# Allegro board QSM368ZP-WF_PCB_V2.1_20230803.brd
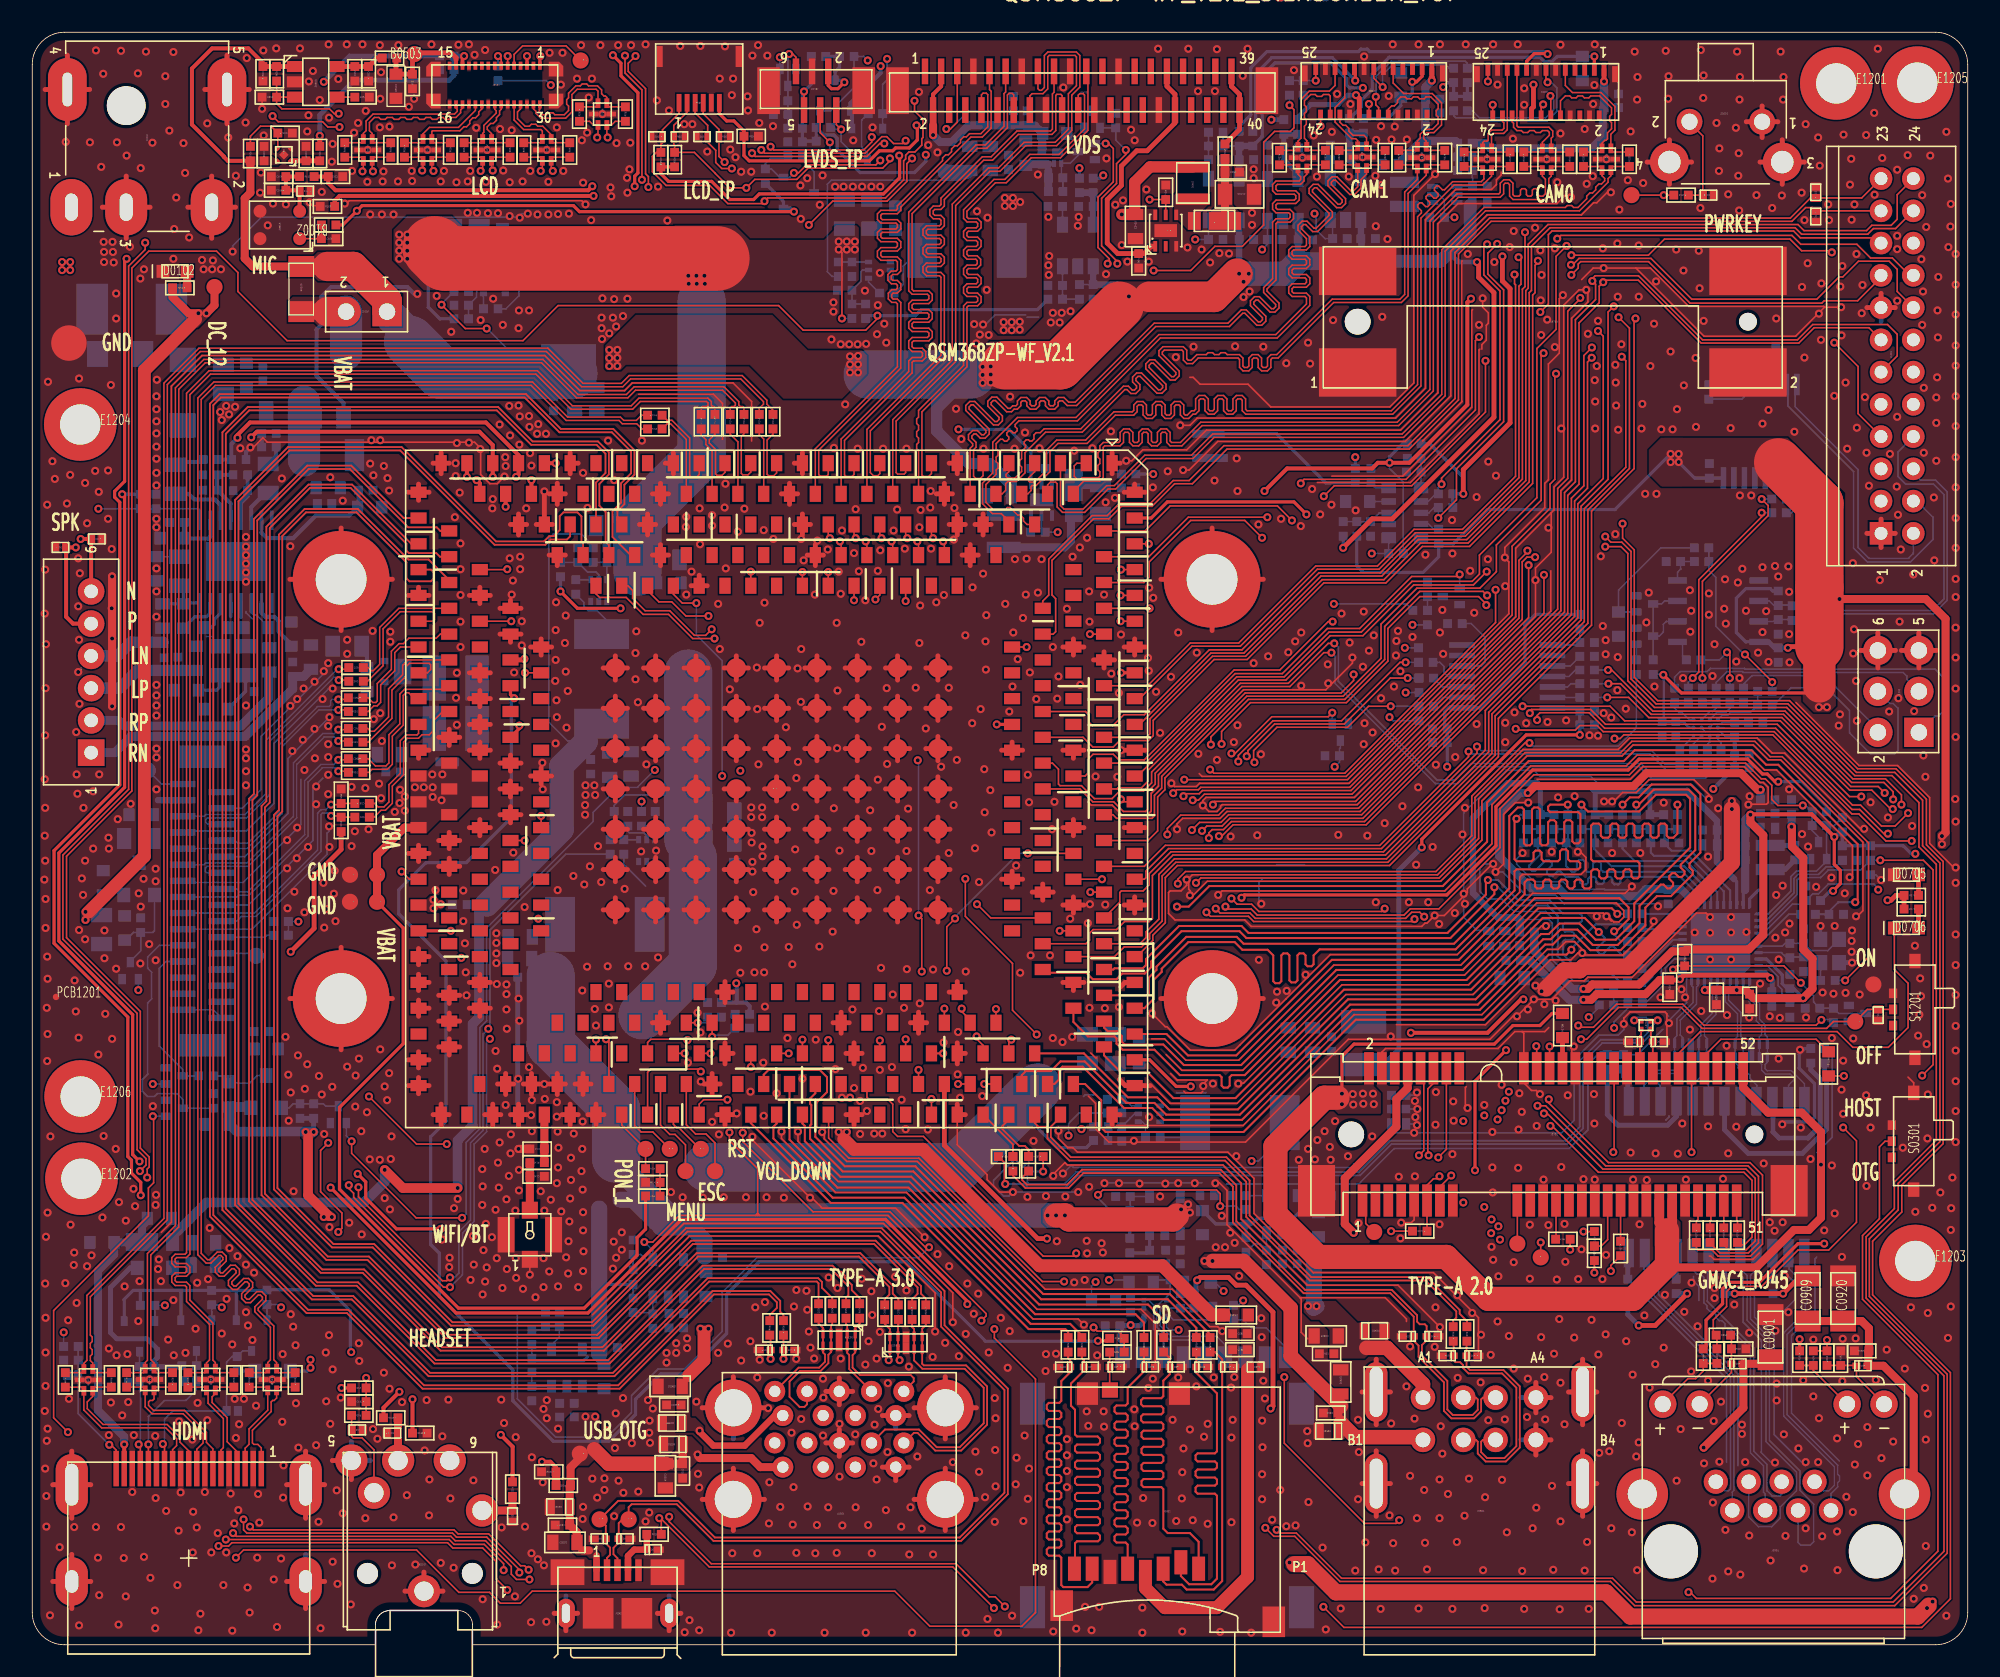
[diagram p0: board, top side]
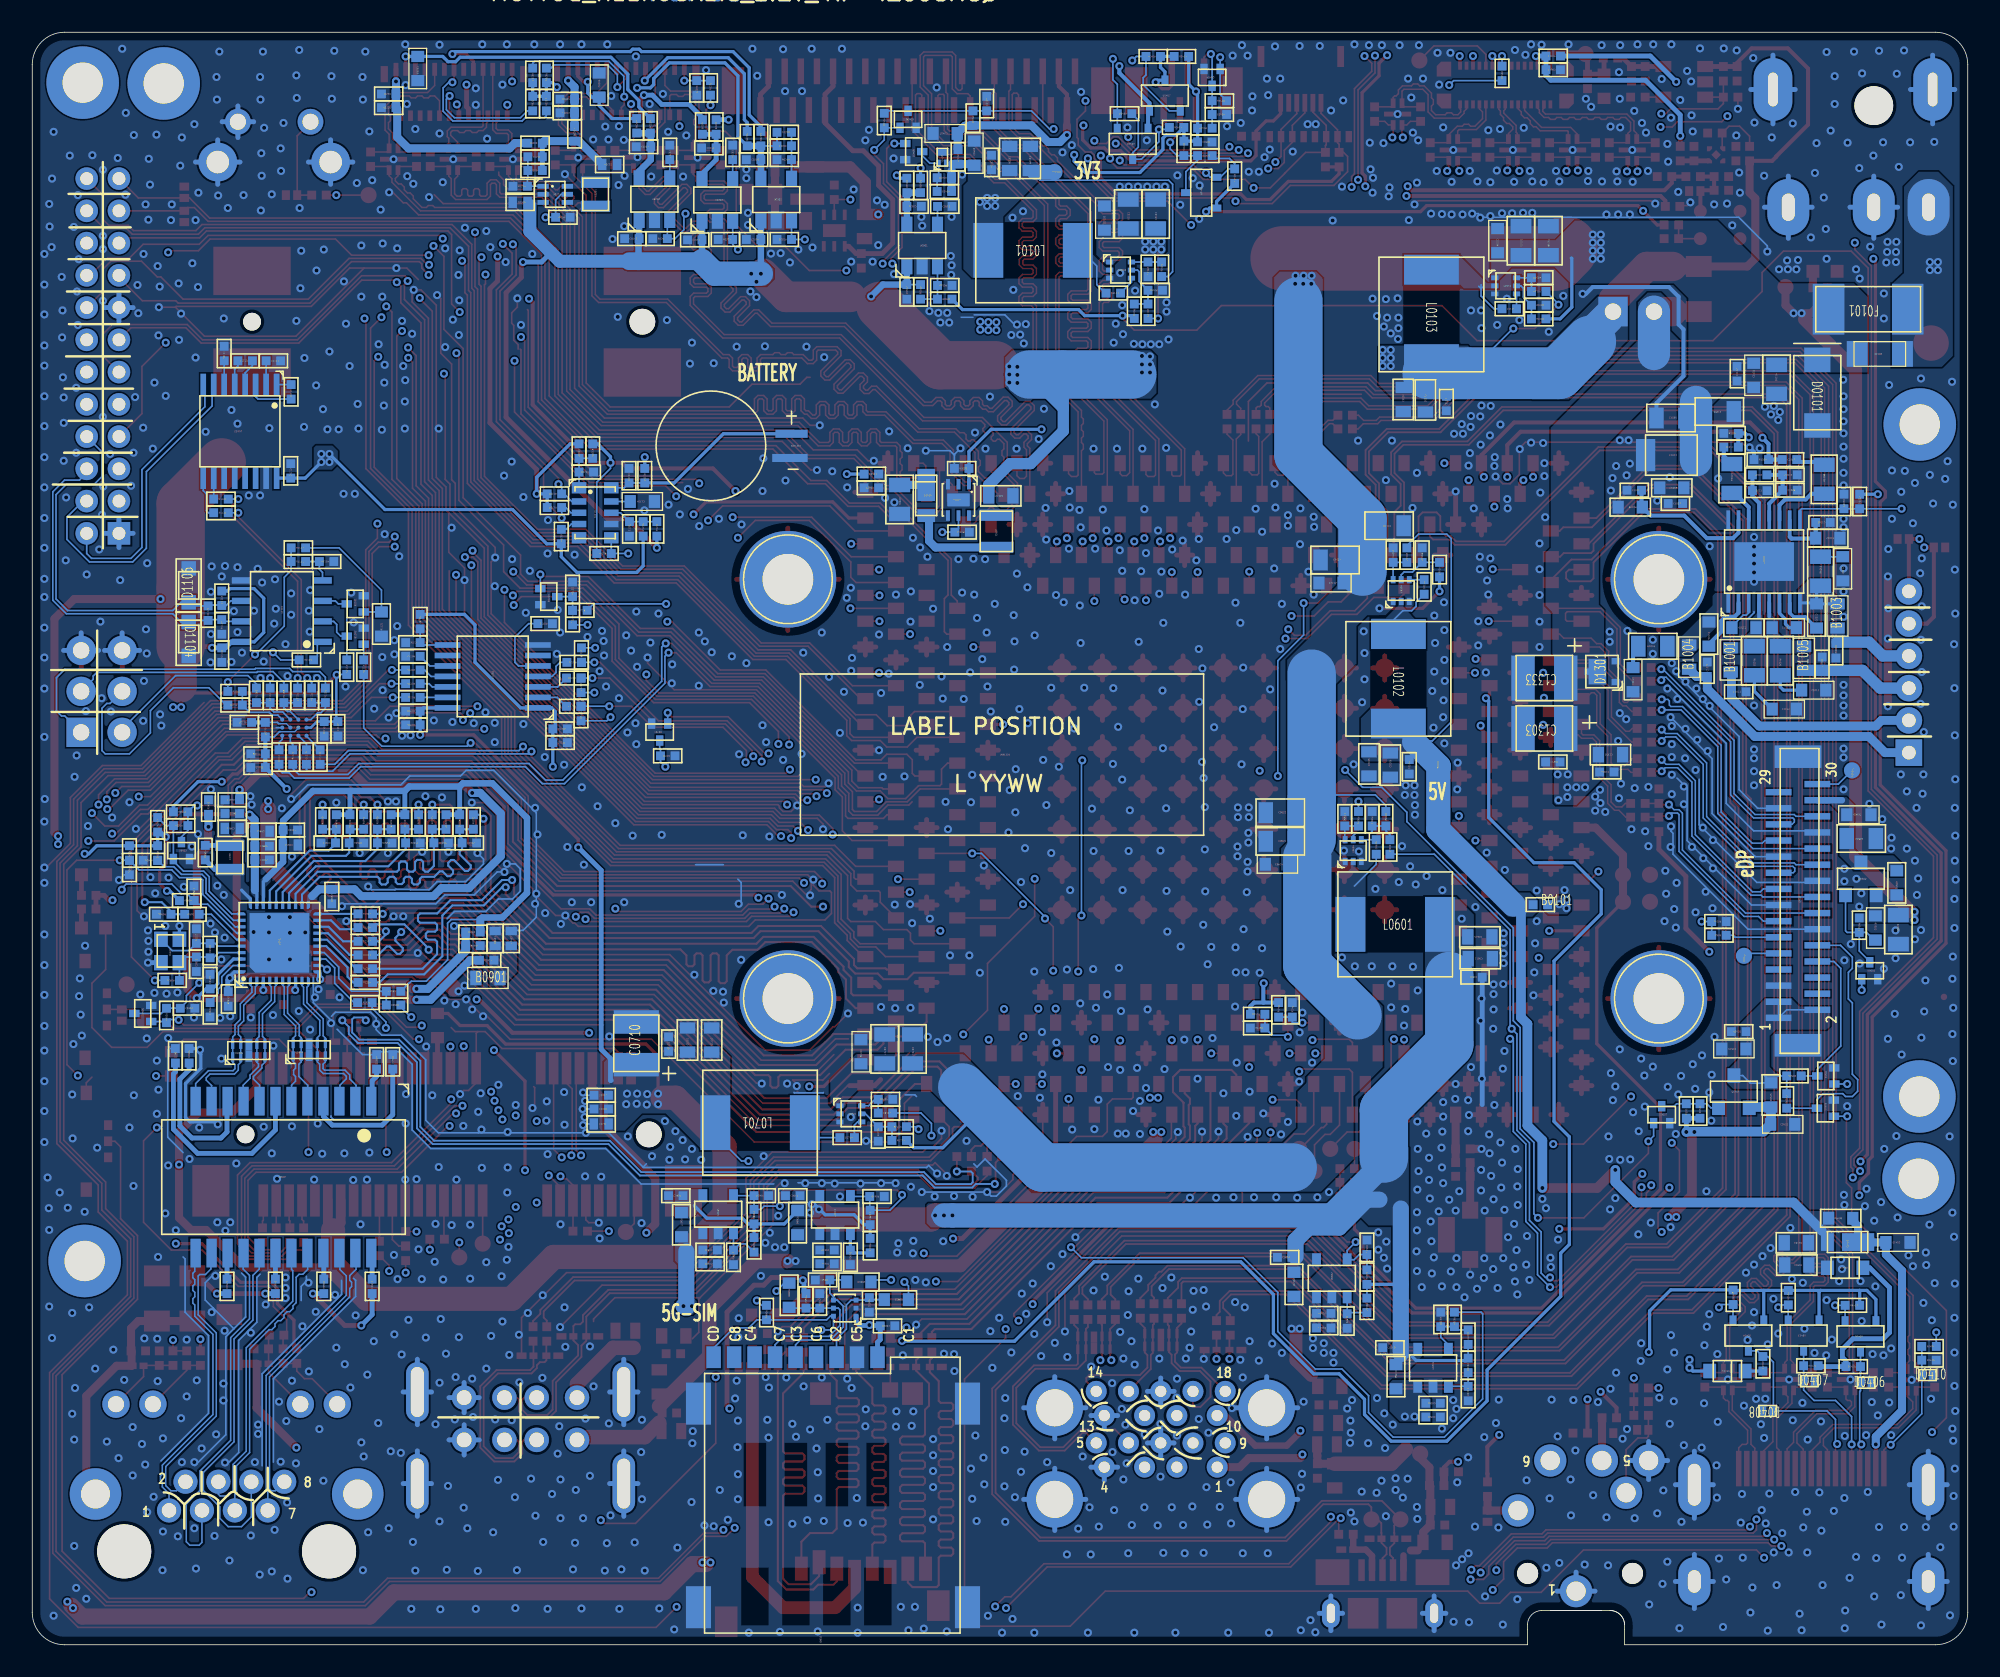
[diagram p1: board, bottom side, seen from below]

Outline 120 x 100 mm; copper layers: TOP, INNER LAYER 2, INNER LAYER 3, BOTTOM. Coordinates in mm from the lower left corner of the outline.
Outline path: 21.27,1.25 arc(21.55,1.87) 22.18,2.12 ; 21.27,1.25 arc(21.55,1.87) 22.18,2.12 ; 21.27,1.25 arc(21.27,1.09) 21.27,0.93 21.27,0 2,0 arc(0.59,0.59) 0,2 0,98 arc(0.59,99.41) 2,100 118,100 arc(119.41,99.41) 120,98 120,2 arc(119.41,0.59) 118,0 27.3,0 27.3,0.93 arc(27.3,1.09) 27.3,1.25 arc(27.03,1.87) 26.4,2.12 22.18,2.12 ; 22.68,2.12 25.9,2.12

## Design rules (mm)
net group 50OHM_ANTWIFI0: nets 50OHM_ANTWIFI0 50OHM_WIFI_ANT0
net group 50OHM_GMAC1_RXCLK_M1: nets 50OHM_GMAC1_RXCLK_M1 50OHM_RXC/PHYAD1_A
net group 50OHM_GMAC1_RXD0_M1: nets 50OHM_GMAC1_RXD0_M1 50OHM_RXD0/RXDLY_A
net group 50OHM_GMAC1_RXD1_M1: nets 50OHM_GMAC1_RXD1_M1 50OHM_RXD1/CFG_MODEO_A
net group 50OHM_GMAC1_RXD2_M1: nets 50OHM_GMAC1_RXD2_M1 50OHM_RXD2/CFG_MODE1_A
net group 50OHM_GMAC1_RXD3_M1: nets 50OHM_GMAC1_RXD3_M1 50OHM_RXD3/CFG_MODE2_A
net group 50OHM_GMAC1_RXDV_CRS_M1: nets 50OHM_GMAC1_RXDV_CRS_M1 50OHM_RXCTL/PHYAD2_A
net group 50OHM_GMAC1_TXCLK: nets 50OHM_GMAC1_TXCLK 50OHM_GMAC1_TXCLK_M1
net group 50OHM_GMAC1_TXD0: nets 50OHM_GMAC1_TXD0 50OHM_GMAC1_TXD0_M1
net group 50OHM_GMAC1_TXD1: nets 50OHM_GMAC1_TXD1 50OHM_GMAC1_TXD1_M1
net group 50OHM_GMAC1_TXD2: nets 50OHM_GMAC1_TXD2 50OHM_GMAC1_TXD2_M1
net group 50OHM_GMAC1_TXD3: nets 50OHM_GMAC1_TXD3 50OHM_GMAC1_TXD3_M1
net group 50OHM_GMAC1_TXEN: nets 50OHM_GMAC1_TXEN 50OHM_GMAC1_TXEN_M1
net group 50OHM_SDMMC0_CLK: nets 50OHM_SDMMC0_CLK 50OHM_SDMMC0_CLK1
net group 50OHM_SDMMC0_CMD: nets 50OHM_SDMMC0_CMD 50OHM_SDMMC0_CMD1
net group 50OHM_SDMMC0_D0: nets 50OHM_SDMMC0_D0 50OHM_SDMMC0_D0_1
net group 50OHM_SDMMC0_D1: nets 50OHM_SDMMC0_D1 50OHM_SDMMC0_D1_1
net group 50OHM_SDMMC0_D2/ARMJTAG_TCK: nets 50OHM_SDMMC0_D2/ARMJTAG_TCK 50OHM_SDMMC0_D2/ARMJTAG_TCK1
net group 50OHM_SDMMC0_D3/ARMJTAG_TMS: nets 50OHM_SDMMC0_D3/ARMJTAG_TMS 50OHM_SDMMC0_D3/ARMJTAG_TMS1
net group 90OHM_D: nets 90OHM_DM 90OHM_DP
net group 90OHM_USB2_HOST2_D_B: nets 90OHM_USB2_HOST2_DM_B 90OHM_USB2_HOST2_DP_B
net group 90OHM_USB2_HOST2_DM: nets 90OHM_USB2_HOST2_DM 90OHM_USB2_HOST2_DM_A
net group 90OHM_USB2_HOST2_DP: nets 90OHM_USB2_HOST2_DP 90OHM_USB2_HOST2_DP_A
net group 90OHM_USB2_HOST3_DM: nets 90OHM_USB2_HOST3_DM 90OHM_USB2_HOST3_DM_A
net group 90OHM_USB2_HOST3_DP: nets 90OHM_USB2_HOST3_DP 90OHM_USB2_HOST3_DP_A
net group 90OHM_USB3_HOST1_DM: nets 90OHM_USB3_HOST1_DM 90OHM_USB3_HOST1_DM_A
net group 90OHM_USB3_HOST1_DP: nets 90OHM_USB3_HOST1_DP 90OHM_USB3_HOST1_DP_A
net group 90OHM_USB3_HOST1_SSRXN: nets 90OHM_USB3_HOST1_SSRXN 90OHM_USB3_HOST1_SSRXN_A1
net group 90OHM_USB3_HOST1_SSRXP: nets 90OHM_USB3_HOST1_SSRXP 90OHM_USB3_HOST1_SSRXP_A1
net group 90OHM_USB3_HOST1_SSTXN: nets 90OHM_USB3_HOST1_SSTXN 90OHM_USB3_HOST1_SSTXN_A1
net group 90OHM_USB3_HOST1_SSTXP: nets 90OHM_USB3_HOST1_SSTXP 90OHM_USB3_HOST1_SSTXP_A1
net group 90OHM_USB3_OTG0_D: nets 90OHM_USB3_OTG0_DM 90OHM_USB3_OTG0_DP
net group 90OHM_USB3_OTG0_SSRXN: nets 90OHM_USB3_OTG0_SSRX_N 90OHM_USB3_OTG0_SSRXN
net group 90OHM_USB3_OTG0_SSRXP: nets 90OHM_USB3_OTG0_SSRX_P 90OHM_USB3_OTG0_SSRXP
net group 90OHM_USB3_OTG0_SSTXN: nets 90OHM_USB3_OTG0_SSTX_N 90OHM_USB3_OTG0_SSTXN
net group 90OHM_USB3_OTG0_SSTXP: nets 90OHM_USB3_OTG0_SSTX_P 90OHM_USB3_OTG0_SSTXP
net group 100OHM_EDP_TX_AUXN: nets 100OHM_EDP_TX_AUXN 100OHM_EDP_TX_AUXN1
net group 100OHM_EDP_TX_AUXP: nets 100OHM_EDP_TX_AUXP 100OHM_EDP_TX_AUXP1
net group 100OHM_EDP_TX_D0N: nets 100OHM_EDP_TX_D0N 100OHM_EDP_TX_D0N1
net group 100OHM_EDP_TX_D0P: nets 100OHM_EDP_TX_D0P 100OHM_EDP_TX_D0P1
net group 100OHM_EDP_TX_D1N: nets 100OHM_EDP_TX_D1N 100OHM_EDP_TX_D1N1
net group 100OHM_EDP_TX_D1P: nets 100OHM_EDP_TX_D1P 100OHM_EDP_TX_D1P1
net group 100OHM_EDP_TX_D2N: nets 100OHM_EDP_TX_D2N 100OHM_EDP_TX_D2N1
net group 100OHM_EDP_TX_D2P: nets 100OHM_EDP_TX_D2P 100OHM_EDP_TX_D2P1
net group 100OHM_EDP_TX_D3N: nets 100OHM_EDP_TX_D3N 100OHM_EDP_TX_D3N1
net group 100OHM_EDP_TX_D3P: nets 100OHM_EDP_TX_D3P 100OHM_EDP_TX_D3P1
net group 100OHM_LAN0_MDI0_A: nets 100OHM_LAN0_MDI0N_A 100OHM_LAN0_MDI0P_A
net group 100OHM_LAN0_MDI1_A: nets 100OHM_LAN0_MDI1N_A 100OHM_LAN0_MDI1P_A
net group 100OHM_LAN0_MDI2_A: nets 100OHM_LAN0_MDI2N_A 100OHM_LAN0_MDI2P_A
net group 100OHM_LAN0_MDI3_A: nets 100OHM_LAN0_MDI3N_A 100OHM_LAN0_MDI3P_A
net group 100OHM_LAN0_RJ45_D0_A: nets 100OHM_LAN0_RJ45_D0M_A 100OHM_LAN0_RJ45_D0P_A
net group 100OHM_LAN0_RJ45_D1_A: nets 100OHM_LAN0_RJ45_D1M_A 100OHM_LAN0_RJ45_D1P_A
net group 100OHM_LAN0_RJ45_D2_A: nets 100OHM_LAN0_RJ45_D2M_A 100OHM_LAN0_RJ45_D2P_A
net group 100OHM_LAN0_RJ45_D3_A: nets 100OHM_LAN0_RJ45_D3M_A 100OHM_LAN0_RJ45_D3P_A
net group 100OHM_MIPI_CSI_RX_CLK0N: nets 100OHM_MIPI_CSI_RX_CLK0N 100OHM_MIPI_CSI_RX_CLK0N1
net group 100OHM_MIPI_CSI_RX_CLK0P: nets 100OHM_MIPI_CSI_RX_CLK0P 100OHM_MIPI_CSI_RX_CLK0P1
net group 100OHM_MIPI_CSI_RX_CLK1N: nets 100OHM_MIPI_CSI_RX_CLK1N 100OHM_MIPI_CSI_RX_CLK1N1
net group 100OHM_MIPI_CSI_RX_CLK1P: nets 100OHM_MIPI_CSI_RX_CLK1P 100OHM_MIPI_CSI_RX_CLK1P1
net group 100OHM_MIPI_CSI_RX_D0N: nets 100OHM_MIPI_CSI_RX_D0N 100OHM_MIPI_CSI_RX_D0N1
net group 100OHM_MIPI_CSI_RX_D0P: nets 100OHM_MIPI_CSI_RX_D0P 100OHM_MIPI_CSI_RX_D0P1
net group 100OHM_MIPI_CSI_RX_D1N: nets 100OHM_MIPI_CSI_RX_D1N 100OHM_MIPI_CSI_RX_D1N1
net group 100OHM_MIPI_CSI_RX_D1P: nets 100OHM_MIPI_CSI_RX_D1P 100OHM_MIPI_CSI_RX_D1P1
net group 100OHM_MIPI_CSI_RX_D2N: nets 100OHM_MIPI_CSI_RX_D2N 100OHM_MIPI_CSI_RX_D2N1
net group 100OHM_MIPI_CSI_RX_D2P: nets 100OHM_MIPI_CSI_RX_D2P 100OHM_MIPI_CSI_RX_D2P1
net group 100OHM_MIPI_CSI_RX_D3N: nets 100OHM_MIPI_CSI_RX_D3N 100OHM_MIPI_CSI_RX_D3N1
net group 100OHM_MIPI_CSI_RX_D3P: nets 100OHM_MIPI_CSI_RX_D3P 100OHM_MIPI_CSI_RX_D3P1
net group 100OHM_MIPI_DSI_TX1_CLKN: nets 100OHM_MIPI_DSI_TX1_CLKN 100OHM_MIPI_DSI_TX1_CLKN_1
net group 100OHM_MIPI_DSI_TX1_CLKP: nets 100OHM_MIPI_DSI_TX1_CLKP 100OHM_MIPI_DSI_TX1_CLKP_1
net group 100OHM_MIPI_DSI_TX1_D0N: nets 100OHM_MIPI_DSI_TX1_D0N 100OHM_MIPI_DSI_TX1_D0N_1
net group 100OHM_MIPI_DSI_TX1_D0P: nets 100OHM_MIPI_DSI_TX1_D0P 100OHM_MIPI_DSI_TX1_D0P_1
net group 100OHM_MIPI_DSI_TX1_D1N: nets 100OHM_MIPI_DSI_TX1_D1N 100OHM_MIPI_DSI_TX1_D1N_1
net group 100OHM_MIPI_DSI_TX1_D1P: nets 100OHM_MIPI_DSI_TX1_D1P 100OHM_MIPI_DSI_TX1_D1P_1
net group 100OHM_MIPI_DSI_TX1_D2N: nets 100OHM_MIPI_DSI_TX1_D2N 100OHM_MIPI_DSI_TX1_D2N_1
net group 100OHM_MIPI_DSI_TX1_D2P: nets 100OHM_MIPI_DSI_TX1_D2P 100OHM_MIPI_DSI_TX1_D2P_1
net group 100OHM_MIPI_DSI_TX1_D3N: nets 100OHM_MIPI_DSI_TX1_D3N 100OHM_MIPI_DSI_TX1_D3N_1
net group 100OHM_MIPI_DSI_TX1_D3P: nets 100OHM_MIPI_DSI_TX1_D3P 100OHM_MIPI_DSI_TX1_D3P_1
net group AVDD33_A: nets DVDD3V3_A ETH_3V3_A
net group FSPI_CS0N/FLASH_CS0N: nets FSPI_CS0N/FLASH_CS0N N18198024
net group GMAC1_MDC_M1: nets GMAC1_MDC_M1 N16865348
net group GMAC1_MDIO_M1: nets GMAC1_MDIO_M1 N16865312
net group GPIO4_B2: nets GPIO4_B2 INTB_A
net group GPIO4_C2: nets GPIO4_C2 N17980948
net group HPL_OUT: nets HPL_OUT N16818791
net group HPR_OUT: nets HPR_OUT N18073365
net group I2S3_SDIM1: nets I2S3_SDIM1 N19352448
net group LCDC_D15: nets LCDC_D15 PHYRSTB_A
net group LCDC_D21: nets LCDC_D21 LVDS_RESET
net group LCDC_HSYNC: nets LCDC_HSYNC N16762456
net group LCMIO_1V8: nets LCMIO_1V8 VCCA1V8_IMAGE
net group LVDS_TP_RST: nets LVDS_TP_RST PDM_SDI2_M0_ADC
net group MIC1_INP: nets MIC1_INP N18080454
net group MINI-PCIE_DTR: nets MINI-PCIE_DTR N19358768
net group N18646284: nets N18646284 N18932423
net group UART4_RXD: nets N16980064 UART4_RXD
net group UART4_TXD: nets N16980060 UART4_TXD
net group UART5_RXD: nets N16980062 UART5_RXD
net group UART5_TXD: nets N16980078 UART5_TXD
net group UART7_TXD: nets N19347930 UART7_TXD
net group 100OHM_HDMI_CLK_N_1: nets 100OHM_HDMI_CLK_N_1 100OHM_HDMI_TXCLKN_PORT 100OHM_HDMI_TXCLKN_PORT1
net group 100OHM_HDMI_CLK_P_1: nets 100OHM_HDMI_CLK_P_1 100OHM_HDMI_TXCLKP_PORT 100OHM_HDMI_TXCLKP_PORT1
net group 100OHM_HDMI_TX0N_PORT: nets 100OHM_HDMI_TX0_N_1 100OHM_HDMI_TX0N_PORT 100OHM_HDMI_TX0N_PORT1
net group 100OHM_HDMI_TX0P_PORT: nets 100OHM_HDMI_TX0_P_1 100OHM_HDMI_TX0P_PORT 100OHM_HDMI_TX0P_PORT1
net group 100OHM_HDMI_TX1N_PORT: nets 100OHM_HDMI_TX1_N_1 100OHM_HDMI_TX1N_PORT 100OHM_HDMI_TX1N_PORT1
net group 100OHM_HDMI_TX1P_PORT: nets 100OHM_HDMI_TX1_P_1 100OHM_HDMI_TX1P_PORT 100OHM_HDMI_TX1P_PORT1
net group 100OHM_HDMI_TX2N_PORT: nets 100OHM_HDMI_TX2_N_1 100OHM_HDMI_TX2N_PORT 100OHM_HDMI_TX2N_PORT1
net group 100OHM_HDMI_TX2P_PORT: nets 100OHM_HDMI_TX2_P_1 100OHM_HDMI_TX2P_PORT 100OHM_HDMI_TX2P_PORT1
net group AUDIO: nets HP_SNS MIC1_INN SPK_OUT_RN SPK_OUT_RP SPKP_OUT
net group AVDD10_A: nets AVDD10_A N18035182 REGOUT_A
net group EXT_EN: nets EXT_EN N16851388 N17316601 N17391886
net group GPIO1_D4: nets GPIO1_D4 MINI-PCIE-C_DTR N19358667
net group LED1/CFG_LDO0_A: nets LED1/CFG_LDO0_A N15680148 N15680388
net group LED2/CFG_LDO1_A: nets LED2/CFG_LDO1_A N15680410 N15680444
net group MODULE_4G_3V5: nets N16421517
net group N17312557: nets N17312557
net group N17316611: nets N17316611
net group N17321453: nets N17321453
net group N17391896: nets N17391896
net group S-50OHM: nets 50OHM_GMAC1_MCLKINOUT_M1
net group UART4_RXD_3.3V: nets N19156807 UART4_RX_3.3V UART4_RXD_3.3V
net group UART4_TXD_3.3V: nets N19156822 UART4_TX_3.3V UART4_TXD_3.3V
net group UART5_RXD_3.3V: nets N19156624 UART5_RX_3.3V UART5_RXD_3.3V
net group UART5_TXD_3.3V: nets N19156735 UART5_TX_3.3V UART5_TXD_3.3V
net group VCCIO4: nets N17593444 VCC_PMUIO2 VCCIO4

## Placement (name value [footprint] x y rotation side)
B0101  B  [B-0402]  26.5 45.9 180 bottom
B0201  600ohm@100MHZ DCR=0.6ohm 300mA  [R-0402]  77.6 94.12 90 bottom
B0202  600ohm@100MHZ DCR=0.6ohm 300mA  [R-0402]  88.83 93.12 0 bottom
B0203  600ohm@100MHZ DCR=0.6ohm 300mA  [R-0402]  86.38 93.7 90 bottom
B0204  600ohm@100MHZ DCR=0.6ohm 300mA  [R-0402]  78.45 94.12 90 bottom
B0205  600ohm@100MHZ DCR=0.6ohm 300mA  [R-0402]  74.83 93.4 90 bottom
B0206  600ohm@100MHZ DCR=0.6ohm 300mA  [R-0402]  75.67 93.4 90 bottom
B0501  600ohm@100MHZ DCR=0.6ohm 300mA  [R-0402]  64.92 90.5 90 bottom
B0502  600ohm@100MHZ DCR=0.6ohm 300mA  [R-0402]  65.78 90.5 90 bottom
B0503  600ohm@100MHZ DCR=0.6ohm 300mA  [B-0402]  22.15 98.4 0 top
B0901  100ohm@100MHz DCR=0.030ohm 3.0A  [B-0603_H0_95]  91.75 41.35 180 bottom
B1001  NM-100ohm@100MHz DCR=0.030ohm 3.0A  [B-0603_H0_95]  14.7 61.08 90 bottom
B1002  600ohm@100MHZ DCR=0.6ohm 300mA  [B-0402]  18.38 88.05 180 top
B1003  NM-100ohm@100MHz DCR=0.030ohm 3.0A  [B-0603_H0_95]  8.07 63.8 90 bottom
B1004  NM-100ohm@100MHz DCR=0.030ohm 3.0A  [B-0603_H0_95]  17.27 61.25 90 bottom
B1005  NM-100ohm@100MHz DCR=0.030ohm 3.0A  [B-0603_H0_95]  10.15 61.17 90 bottom
BAT1201  NM-MS621FE-FL11E  [MS621FE-FL11E]  72.83 74.35 180 bottom
C0102  100nF +/-10% 50V  [C-0603]  53.52 88.47 270 bottom
C0103  NM-100nF +/-10% 50V  [C-0603]  13.28 78.72 90 bottom
C0104  1uF +/-10% 10V  [C-0402]  34.62 54.45 90 bottom
C0105  22uF +/-20% 10V  [C-0603_22_47UF_H1_00]  37.12 54.62 90 bottom
C0106  22uF +/-20% 10V  [C-0603_22_47UF_H1_00]  35.8 54.55 90 bottom
C0107  22uF +/-20% 6.3V  [C-0603_22_47UF_H1_00]  35 77.22 90 bottom
C0108  NM-22uF +/-20% 25V  [C-0805_H1_45]  26 87.08 270 bottom
C0109  22uF +/-20% 6.3V  [C-0603_22_47UF_H1_00]  58.12 92.17 270 bottom
C0110  10uF +/-10% 16V  [C-0805_H1_45]  27.7 87.08 270 bottom
C0111  100nF +/-10% 16V  [C-0402]  28.43 82.85 180 bottom
C0112  100nF +/-10% 50V  [C-0603]  39.48 65.85 180 bottom
C0113  100nF +/-10% 16V  [C-0402]  52.98 83.83 180 bottom
C0114  100nF +/-10% 16V  [C-0402]  33.7 65.6 90 bottom
C0115  10uF +/-10% 16V  [C-0805_H1_45]  52.05 88.72 270 bottom
C0116  NM-22uF +/-20% 25V  [C-0805_H1_45]  11.85 78.47 90 bottom
C0118  NM-22uF +/-20% 25V  [C-0805_H1_45]  35.88 69.4 0 bottom
C0119  1uF +/-10% 6.3V  [C-0402]  32.33 76.97 90 bottom
C0121  NM-22uF +/-20% 25V  [C-0805_H1_45]  50.35 88.72 270 bottom
C0122  NM-33pF +/-5% 50V  [C-0402]  14.3 78.83 90 bottom
C0123  22uF +/-20% 6.3V  [C-0603_22_47UF_H1_00]  33.62 77.2 90 bottom
C0124  1uF +/-10% 6.3V  [C-0402]  60.52 91.92 270 bottom
C0126  22uF +/-20% 6.3V  [C-0603_22_47UF_H1_00]  59.4 92.17 270 bottom
C0127  10uF +/-10% 16V  [C-0805_H1_45]  39.23 67.28 180 bottom
C0128  100nF +/-10% 50V  [C-0603]  29.15 87.08 270 bottom
C0201  100nF +/-10% 10V  [C-0402]  97.9 96.17 0 bottom
C0202  100nF +/-10% 10V  [C-0402]  86.83 95.85 0 bottom
C0203  4.7uF +/-10% 6.3V  [C-0603]  96.1 97.75 270 bottom
C0204  1uF +/-10% 10V  [C-0402]  75.28 87.15 180 bottom
C0205  10uF +/-20% 10V  [C-0402_4_7_10UF_H0_70]  89.75 89.45 180 bottom
C0206  4.7uF +/-10% 6.3V  [C-0603]  84.85 96.72 90 bottom
C0207  10nF +/-10% 16V  [C-0402]  80.47 92.55 270 bottom
C0208  10uF +/-20% 10V  [C-0402_4_7_10UF_H0_70]  84.2 91.8 0 bottom
C0209  1uF +/-10% 10V  [C-0402]  75.28 92.1 180 bottom
C0210  1uF +/-10% 10V  [C-0402]  97.9 95.33 0 bottom
C0211  33pF +/-5% 50V  [C-0402]  88.83 92.28 180 bottom
C0212  1uF +/-10% 10V  [C-0402]  78.05 92.83 180 bottom
C0213  1uF +/-10% 10V  [C-0402]  82.83 87.2 180 bottom
C0214  1uF +/-10% 10V  [C-0402]  86.83 95 0 bottom
C0215  1uF +/-10% 10V  [C-0402]  78.92 87.12 180 bottom
C0216  10nF +/-10% 16V  [C-0402]  76.58 92.55 270 bottom
C0217  1uF +/-10% 10V  [C-0402]  82.1 92.9 180 bottom
C0299  1.0nF +/-10% 50V  [C-0402]  73.38 93.8 180 bottom
C0301  100nF +/-10% 10V  [C-0402]  33.15 14.97 0 bottom
C0303  1uF +/-10% 10V  [C-0402]  33.15 14.12 0 bottom
C0307  100nF +/-10% 10V  [C-0402]  53.7 20.62 90 top
C0309  100nF +/-10% 10V  [C-0402]  52.85 20.62 90 top
C0319  1uF +/-10% 10V  [C-0402]  35.83 18.43 180 bottom
C0352  22uF +/-20% 10V  [C-0603_22_47UF_H1_00]  33.02 6.35 180 top
C0353  100nF +/-10% 16V  [C-0402]  32.88 7.42 180 top
C0354  22uF +/-20% 10V  [C-0603_22_47UF_H1_00]  39.25 10.47 270 top
C0355  100nF +/-10% 16V  [C-0402]  40.33 10.78 270 top
C0360  100nF +/-10% 16V  [C-0402]  48.75 20.7 90 top
C0361  100nF +/-10% 16V  [C-0402]  49.6 20.7 90 top
C0362  100nF +/-10% 16V  [C-0402]  39.77 14.88 0 top
C0363  22uF +/-20% 10V  [C-0603_22_47UF_H1_00]  39.55 16.02 0 top
C0401  22uF +/-20% 10V  [C-0603_22_47UF_H1_00]  10.6 23.55 180 bottom
C0402  22uF +/-20% 6.3V  [C-0603_22_47UF_H1_00]  68.4 87.95 90 top
C0403  1uF +/-10% 10V  [C-0402]  47.3 93.2 180 bottom
C0404  NM-100nF +/-10% 10V  [C-0402]  60.83 95.58 90 bottom
C0405  100nF +/-10% 10V  [C-0402]  63.45 90.12 180 bottom
C0406  NM-100nF +/-10% 10V  [C-0402]  46.4 94.9 180 bottom
C0407  4.7uF +/-10% 6.3V  [C-0603]  63.4 93.72 0 bottom
C0408  1.0nF +/-10% 50V  [C-0402]  74.4 91.33 0 top
C0409  4.7uF +/-10% 6.3V  [C-0603]  61.6 92.5 90 bottom
C0410  10uF +/-20% 10V  [C-0603_22_47UF_H1_00]  10.62 24.93 180 bottom
C0412  1uF +/-10% 50V  [C-0805]  74.85 89.95 0 top
C0413  1uF +/-10% 16V  [C-0603]  4.33 24.95 0 bottom
C0501  NM-2.2uF +/-10% 10V  [C-0402]  14.38 92.47 270 top
C0502  1uF +/-10% 6.3V  [C-0402]  65.78 83.9 90 bottom
C0504  1uF +/-10% 50V  [C-0805]  66.22 71.03 270 bottom
C0505  NM-100nF +/-10% 16V  [C-0402]  20.05 57.88 180 top
C0506  NM-100nF +/-10% 50V  [C-0603]  6.75 51.48 0 bottom
C0507  100nF +/-10% 16V  [C-0402]  23.57 96.95 270 top
C0508  4.7uF +/-10% 6.3V  [C-0603]  22.55 96.65 270 top
C0509  NM-100nF +/-10% 16V  [C-0402]  20.05 54.95 0 top
C0510  NM-100nF +/-10% 16V  [C-0402]  20.07 60.6 0 top
C0511  10nF +/-10% 50V  [C-0402]  63.42 89.2 180 bottom
C0512  22uF +/-20% 6.3V  [C-0603_22_47UF_H1_00]  59.95 71.25 0 bottom
C0513  NM-100nF +/-10% 16V  [C-0402]  20.05 55.98 180 top
C0514  10nF +/-10% 50V  [C-0402]  20.45 95.97 0 top
C0515  NM-100nF +/-10% 16V  [C-0402]  20.45 51.33 0 top
C0516  NM-100nF +/-10% 50V  [C-0603]  5.72 44.45 90 bottom
C0517  NM-100nF +/-10% 10V  [C-0402]  17.45 33.1 270 bottom
C0518  NM-100nF +/-10% 10V  [C-0402]  14.2 38.02 0 bottom
C0519  1uF +/-10% 6.3V  [C-0402]  25.7 97.67 0 bottom
C0520  NM-22uF +/-20% 25V  [C-0805_H1_45]  4.3 44.35 90 bottom
C0521  NM-4.7uF +/-10% 6.3V  [C-0603]  11.47 32.27 180 bottom
C0522  NM-10uF +/-10% 16V  [C-0805_H1_45]  6.6 50 0 bottom
C0523  NM-4.7uF +/-10% 6.3V  [C-0603]  14.5 36.95 0 bottom
C0524  2.2uF +/-20% 6.3V  [C-0402]  20 97.42 90 top
C0525  NM-100nF +/-10% 16V  [C-0402]  15.68 93.75 180 top
C0526  1uF +/-10% 6.3V  [C-0402]  65.33 89.2 0 bottom
C0527  1.0nF +/-10% 50V  [C-0402]  67.97 71.75 0 bottom
C0528  100nF +/-10% 16V  [C-0402]  20.85 97.42 270 top
C0529  NM-100nF +/-10% 16V  [C-0402]  20.05 58.73 0 top
C0530  1uF +/-10% 10V  [C-0402]  14.3 97.42 270 top
C0531  NM-100nF +/-10% 16V  [C-0402]  20.05 56.83 0 top
C0532  NM-100nF +/-10% 16V  [C-0402]  20.07 59.75 180 top
C0533  100nF +/-10% 16V  [C-0402]  44.58 93.55 0 top
C0534  NM-100nF +/-10% 16V  [C-0402]  20.05 54.1 180 top
C0535  NM-1uF +/-10% 10V  [C-0402]  16.98 92.47 270 top
C0536  NM-100nF +/-10% 16V  [C-0402]  20.45 52.17 180 top
C0601  NM-1uF +/-10% 10V  [C-0402]  80.1 27.85 180 bottom
C0602  1uF +/-10% 10V  [C-0402]  30.55 41.4 0 bottom
C0603  NM-100nF +/-10% 16V  [C-0402]  77.97 23.62 0 bottom
C0604  NM-100nF +/-10% 16V  [C-0402]  39.92 19.65 0 bottom
C0605  22uF +/-20% 10V  [C-0603_22_47UF_H1_00]  80.22 19.15 180 top
C0606  NM-1uF +/-10% 10V  [C-0402]  77.97 24.48 0 bottom
C0607  NM-1uF +/-10% 10V  [C-0402]  42.35 24.02 180 bottom
C0609  NM-1uF +/-10% 10V  [C-0402]  39.92 20.55 0 bottom
C0611  22uF +/-20% 10V  [C-0603_22_47UF_H1_00]  30.23 42.55 0 bottom
C0613  NM-1uF +/-10% 10V  [C-0402]  72.85 27.85 180 bottom
C0614  100nF +/-10% 50V  [C-0603]  42.8 48.4 180 bottom
C0615  22uF +/-20% 10V  [C-0603_22_47UF_H1_00]  30.25 43.9 0 bottom
C0617  NM-100nF +/-10% 16V  [C-0402]  70.72 23.62 0 bottom
C0618  100nF +/-10% 16V  [C-0402]  36.67 49.48 90 bottom
C0619  NM-1uF +/-10% 10V  [C-0402]  70.72 24.48 0 bottom
C0620  100nF +/-10% 16V  [C-0402]  80.25 18.05 180 top
C0621  100nF +/-10% 16V  [C-0402]  80.5 14.38 180 top
C0622  NM-22uF +/-20% 25V  [C-0805_H1_45]  42.62 51.6 180 bottom
C0623  22uF +/-20% 10V  [C-0603_22_47UF_H1_00]  81.12 16.3 90 top
C0624  10uF +/-10% 16V  [C-0805_H1_45]  42.62 49.83 180 bottom
C0701  10pF +/-5% 50V  [C-0402]  80.6 55.12 0 bottom
C0702  100nF +/-10% 16V  [C-0402]  87.28 56.8 180 bottom
C0703  100nF +/-10% 16V  [C-0402]  96.4 57.9 0 bottom
C0704  NM-22uF +/-20% 25V  [C-0805_H1_45]  65.42 36.95 270 bottom
C0705  1uF +/-10% 6.3V  [C-0402]  96.4 57.05 0 bottom
C0706  10pF +/-5% 50V  [C-0402]  86.5 65.45 270 bottom
C0707  33pF +/-5% 50V  [C-0402]  84.72 34.08 180 bottom
C0708  100nF +/-10% 10V  [C-0402]  84.72 33.23 180 bottom
C0709  100nF +/-10% 50V  [C-0603]  68.62 36.77 270 bottom
C0710  100uF +/-20% 6.3V  [3528TB-M]  82.55 37.3 90 bottom
C0711  10uF +/-20% 6.3V  [C-0402_4_7_10UF]  84.72 32.3 180 bottom
C0712  22uF +/-20% 10V  [C-0603_22_47UF_H1_00]  79.38 37.5 270 bottom
C0713  22uF +/-20% 10V  [C-0603_22_47UF_H1_00]  77.88 37.5 270 bottom
C0714  100nF +/-10% 16V  [C-0402]  69.47 31.45 180 bottom
C0715  1uF +/-10% 10V  [C-0402]  80.55 37.25 270 bottom
C0716  1uF +/-10% 6.3V  [C-0402]  87.28 55.95 180 bottom
C0717  10uF +/-10% 16V  [C-0805_H1_45]  67.15 36.95 270 bottom
C0801  100nF +/-10% 10V  [C-0402]  66.97 19.77 0 bottom
C0802  33pF +/-5% 50V  [C-0402]  71 22.62 180 bottom
C0803  2.2uF +/-20% 10V  [C-0402]  74.88 18.3 0 top
C0804  33pF +/-5% 50V  [C-0402]  71.17 21.32 270 bottom
C0805  2.2uF +/-20% 10V  [C-0402]  74.88 19.3 0 top
C0806  33pF +/-5% 50V  [C-0402]  68.1 21.07 90 bottom
C0901  1nF +/-10% 2000V  [C-1206]  107.78 19.07 90 top
C0902  10uF +/-20% 6.3V  [C-0402_4_7_10UF]  91.3 43.8 270 bottom
C0903  NM-100nF +/-10% 10V  [C-0402]  110.38 39.48 180 bottom
C0904  100nF +/-10% 10V  [C-0402]  101.53 40.77 270 top
C0905  100nF +/-10% 10V  [C-0402]  101.42 46.4 270 bottom
C0906  100nF +/-10% 10V  [C-0402]  105.75 49.52 180 bottom
C0907  100nF +/-10% 10V  [C-0402]  107.6 51.55 180 bottom
C0908  100nF +/-10% 10V  [C-0402]  107.85 40.05 270 bottom
C0909  1nF +/-10% 2000V  [C-1206]  110.08 21.48 90 top
C0910  100nF +/-10% 10V  [C-0402]  104.42 40.15 270 top
C0911  4.7uF +/-20% 6.3V  [C-0402_4_7_10UF]  105.75 50.45 0 bottom
C0912  15pF +/-5% 50V  [C-0402]  109.83 42.2 90 bottom
C0913  100nF +/-10% 10V  [C-0402]  106.47 39.9 270 top
C0914  100nF +/-10% 10V  [C-0402]  104 50.52 180 bottom
C0915  100nF +/-10% 10V  [C-0402]  108.97 41.12 90 bottom
C0916  4.7uF +/-20% 6.3V  [C-0402_4_7_10UF]  107.6 50.62 0 bottom
C0917  10uF +/-20% 6.3V  [C-0402_4_7_10UF]  90.3 43.8 270 bottom
C0918  4.7uF +/-20% 6.3V  [C-0402_4_7_10UF]  104 49.6 0 bottom
C0919  100nF +/-10% 10V  [C-0402]  98.65 36.15 90 bottom
C0920  1nF +/-10% 2000V  [C-1206]  112.28 21.48 90 top
C0921  15pF +/-5% 50V  [C-0402]  109.83 43.95 270 bottom
C0922  100nF +/-10% 10V  [C-0402]  105.75 48.67 180 bottom
C0986  100nF +/-10% 10V  [C-0402]  110.28 36.52 90 bottom
C0987  100nF +/-10% 10V  [C-0402]  111.12 36.52 90 bottom
C0988  100nF +/-10% 10V  [C-0402]  97.65 36.15 90 bottom
C1001  NM-1uF +/-10% 16V  [C-0402]  12.9 71.58 0 bottom
C1003  NM-100nF +/-10% 16V  [C-0402]  18.12 70.78 180 bottom
C1004  NM-10nF +/-10% 50V  [C-0603]  20.75 59.85 270 bottom
C1005  NM-2.2uF +/-20% 10V  [C-0402]  8.97 69.6 0 bottom
C1006  NM-1.0nF +/-10% 50V  [C-0402]  8.18 61.65 90 bottom
C1007  NM-10nF +/-10% 50V  [C-0603]  7.75 66.72 270 bottom
C1008  1uF +/-10% 16V  [C-0402]  11.03 71.6 180 bottom
C1009  NM-1.0nF +/-10% 50V  [C-0402]  9.03 60.8 90 bottom
C1010  NM-33pF +/-5% 50V  [C-0402]  18.8 91.05 180 top
C1011  NM-10nF +/-10% 50V  [C-0603]  9.55 59.2 180 bottom
C1012  NM-10nF +/-10% 50V  [C-0603]  11.38 58.02 180 bottom
C1013  NM-100uF +/-20% 16V  [C-1210]  18.38 73.78 180 bottom
C1014  100nF +/-10% 10V  [C-0402]  18.38 87.2 0 top
C1015  NM-33pF +/-5% 50V  [C-0402]  15.28 91.05 0 top
C1016  NM-2.2uF +/-20% 10V  [C-0402]  14.68 74.28 0 bottom
C1017  NM-2.2uF +/-20% 10V  [C-0402]  11.05 73.5 180 bottom
C1018  NM-1uF +/-10% 50V  [C-0603_H1_00]  18.35 71.75 180 bottom
C1020  NM-1uF +/-10% 50V  [C-0603_H1_00]  13.88 63.08 0 bottom
C1021  NM-2.2uF +/-20% 10V  [C-0402]  20.68 71.6 180 bottom
C1022  NM-1uF +/-10% 50V  [C-0603_H1_00]  9.38 63.8 270 bottom
C1023  NM-1.0nF +/-10% 50V  [C-0402]  14.2 59.1 0 bottom
C1024  100nF +/-10% 10V  [C-0402]  20.25 15.07 0 top
C1025  NM-1.0nF +/-10% 50V  [C-0402]  16.15 60.5 90 bottom
C1026  NM-1uF +/-10% 50V  [C-0603_H1_00]  16.05 62.67 270 bottom
C1027  NM-1uF +/-10% 50V  [C-0603_H1_00]  11.38 63.08 180 bottom
C1055  NM-22uF +/-20% 25V  [C-0805_H1_45]  18.4 76.08 180 bottom
C1056  NM-10K +/-1% 1/16W  [C-0805_H1_45]  15.4 76.47 0 bottom
C1099  100pF +/-5% 50V  [C-0402]  15.28 90.2 0 top
C1101  NM-2.2uF +/-10% 6.3V  [C-0402]  103.97 72.8 270 bottom
C1102  100nF +/-10% 10V  [C-0402]  101.9 56.8 270 bottom
C1103  1uF +/-10% 6.3V  [C-0402]  106 54.4 180 bottom
C1104  NM-100nF +/-10% 10V  [C-0402]  108.1 80.08 270 bottom
C1105  NM-100nF +/-10% 10V  [C-0402]  103.95 77.7 270 bottom
C1106  NM-2.2uF +/-10% 6.3V  [C-0402]  108.25 61.38 90 bottom
C1108  100nF +/-10% 10V  [C-0402]  106 55.25 0 bottom
C1110  1uF +/-10% 6.3V  [C-0402]  101.05 56.8 90 bottom
C1111  NM-100nF +/-10% 10V  [C-0402]  105.05 79.62 180 bottom
C1113  NM-100nF +/-10% 10V  [C-0402]  106.8 79.62 0 bottom
C1201  NM-100nF +/-10% 16V  [C-0402]  83 72.5 270 bottom
C1202  NM-100nF +/-10% 16V  [C-0402]  82.97 69.2 90 bottom
C1203  NM-100nF +/-10% 16V  [C-0402]  85.65 72.72 0 bottom
C1204  NM-1uF +/-10% 16V  [C-0603]  82.17 70.9 0 bottom
C1302  22uF +/-20% 10V  [C-0603_22_47UF_H1_00]  22.15 55.2 0 bottom
C1303  100uF +/-20% 6.3V  [3528TB-M]  26.25 56.83 0 bottom
C1304  33pF +/-5% 50V  [C-0402]  22.38 54.12 0 bottom
C1306  100nF +/-10% 10V  [C-0402]  25.73 54.75 180 bottom
C1333  NM-100uF  [3528TB-M]  26.25 59.95 0 bottom
C1401  NM  [C-0402]  31.3 30.75 0 top
C1402  NM  [C-0402]  31.3 29.05 180 top
D0101  -  [SMAJ18CA]  9.32 77.65 270 bottom
D0102  -  [LTST-C193KRKT-5A]  8.85 85.17 0 top
D0301  ESD5304D-10/TR  [ESD5304D-10_TR]  54.17 18.73 0 top
D0302  -  [ESDU5V0F1]  35.15 6.58 180 top
D0303  -  [ESDU5V0F1]  36.75 6.58 0 top
D0353  -  [ESDU5V0F1]  38.5 5.9 0 top
D0354  -  [PTVSHC2EN7VU]  32.7 8.55 180 top
D0355  -  [PTVSHC2EN7VU]  39.73 12.43 180 top
D0356  -  [ESDU5V0F1]  46.98 18.27 0 top
D0357  -  [ESDU5V0F1]  45.38 18.27 180 top
D0358  -  [PTVSHC2EN7VU]  39.65 13.75 180 top
D0359  ESD5304D-10/TR  [ESD5304D-10_TR]  50.02 18.9 180 top
D0401  -  [PSBD3D40V1H]  14.9 16.98 0 bottom
D0402  -  [PSBD3D40V1H]  7.6 23.38 0 bottom
D0403  RB160VAM-40TR  [RB160VA-40]  7.45 24.98 270 bottom
D0404  -  [PNMT60V02]  13.6 19.18 0 bottom
D0405  RB160VAM-40TR  [RB160VA-40]  73.3 88.3 270 top
D0406  -  [PESDNC2FD7VB]  6.3 16.25 180 bottom
D0407  -  [PESDNC2FD7VB]  9.82 16.35 180 bottom
D0408  -  [PESDNC2FD7VB]  12.4 14.5 0 bottom
D0410  -  [PESDNC2FD7VB]  2.5 16.73 180 bottom
D0501  NM-DTC043ZEBTL  [DTC043ZEBTL]  8.8 35.27 90 bottom
D0502  NM-ICMEF112P900MFR  [ICMEF112P900MFR]  31.9 92.7 90 top
D0503  NM-DTC043ZEBTL  [DTC043ZEBTL]  6.08 41.8 180 bottom
D0504  -  [PESD5V0S1BL]  40.12 93.53 180 top
D0505  NM-DTC043ZEBTL  [DTC043ZEBTL]  8.82 33.27 90 bottom
D0506  NM-ICMEF112P900MFR  [ICMEF112P900MFR]  35.35 94.92 90 top
D0507  NM-DTC043ZEBTL  [DTC043ZEBTL]  18.98 32.88 180 bottom
D0508  RB160VAM-40TR  [RB160VA-40]  64.58 71.28 180 bottom
D0509  -  [PESD5V0S1BL]  38.73 93.53 0 top
D0510  -  [PESD5V0S1BL]  42.92 93.53 180 top
D0511  NM-ICMEF112P900MFR  [ICMEF112P900MFR]  24.5 92.7 90 top
D0512  NM-ICMEF112P900MFR  [ICMEF112P900MFR]  28.2 92.7 90 top
D0513  -  [PESD5V0S1BL]  41.52 93.53 0 top
D0514  NM-ICMEF112P900MFR  [ICMEF112P900MFR]  20.8 92.7 90 top
D0601  -  [ESDU5V0F1]  87.72 17.93 180 top
D0602  -  [PTVSHC2EN7VU]  83.22 19.48 0 top
D0603  -  [ESDU5V0F1]  85.25 19.12 180 top
D0605  -  [PTVSHC2EN7VU]  80.38 13.25 180 top
D0606  -  [ESDU5V0F1]  89.33 17.93 0 top
D0608  -  [ESDU5V0F1]  86.85 19.12 0 top
D0701  -  [DTC043ZEBTL]  81.1 56.6 0 bottom
D0702  -  [ESDU5V0F1]  100.88 37.4 0 top
D0703  -  [DTC043ZEBTL]  87.97 65 270 bottom
D0704  -  [ESDU5V0F1]  99.28 37.4 180 top
D0705  -  [LTST-C193KRKT-5A]  116.2 47.75 0 top
D0706  -  [LTST-C193KRKT-5A]  116.2 44.45 0 top
D0801  -  [ESDU5V0F1]  69.33 17.23 0 top
D0802  -  [ESDU5V0F1]  70.92 17.23 0 top
D0803  -  [F-CESDLC5V0M5]  69.62 20.88 90 bottom
D0804  -  [ESDU5V0F1]  63.95 17.23 180 top
D0806  -  [PESDNC2FD5VBH]  75.85 17.23 0 top
D0807  -  [ESDU5V0F1]  72.58 17.23 0 top
D0808  -  [ESDU5V0F1]  67.2 17.23 0 top
D0809  -  [ESDU5V0F1]  74.17 17.23 0 top
D0810  -  [ESDU5V0F1]  65.6 17.23 0 top
D0901  -  [ESDU5V0F1]  113.5 17.3 0 top
D0902  -  [DTC043ZEBTL]  110.75 49.25 180 bottom
D0903  -  [ESDU5V0F1]  105.75 17.43 0 top
D0904  NM-ESD5304D-10/TR  [ESD5304D-10_TR]  102.83 36.9 180 bottom
D0905  -  [DTC043ZEBTL]  113.15 39.15 90 bottom
D0906  NM-ESD5304D-10/TR  [ESD5304D-10_TR]  106.58 36.85 180 bottom
D1001  -  [PESDNC2FD5VBH]  29.77 7.97 270 top
D1002  -  [PESDNC2FD5VBH]  16.93 90.15 0 top
D1003  -  [PESDNC2FD5VBH]  22.32 13.12 180 top
D1004  -  [PESDNC2FD5VBH]  20.15 13.32 0 top
D1050  -  [PESDNC2FD5VBH]  1.75 68.05 180 top
D1051  -  [PESDNC2FD5VBH]  4 68.58 0 top
D1104  NM-PESD24VL1BA  [SOD-323]  110.3 62.38 270 bottom
D1106  NM-PESD24VL1BA  [SOD-323]  110.3 65.7 90 bottom
D1201  -  [PESDNC2FD5VBH]  103.92 89.9 180 top
D1202  -  [PESDNC2FD5VBH]  114.45 39.05 270 top
D1255  -  [PESDNC2FD5VBH]  110.58 88.58 90 top
D1256  -  [PESDNC2FD5VBH]  110.58 90.08 270 top
D1301  -  [PTVSHC3N4V5B]  22.68 60.35 90 bottom
F0101  -  [2410WNF1000A125V]  6.17 82.83 0 bottom
HOLE1201  PTH_cir2_50_4_50  [PTH_CIR2_50_4_50]  111.85 96.83 0 top
HOLE1202  PTH_cir2_50_4_50  [PTH_CIR2_50_4_50]  3.05 28.9 0 top
HOLE1203  PTH_cir2_50_4_50  [PTH_CIR2_50_4_50]  116.75 23.8 0 top
HOLE1204  PTH_cir2_50_4_50  [PTH_CIR2_50_4_50]  2.98 75.67 0 top
HOLE1205  PTH_cir2_50_4_50  [PTH_CIR2_50_4_50]  116.88 96.88 0 top
HOLE1206  PTH_cir2_50_4_50  [PTH_CIR2_50_4_50]  3 34 0 top
J0101  -  [DC-305B209]  7.12 93.55 270 top
J0102  NM-C2542VD10210G0101PK  [C2542VD10210G0101PK]  20.73 82.67 180 top
J0201  FH26W-25S-0.3SHW(60)  [FH26W-25S-0_3SHW_60]  93.85 96.3 180 top
J0202  FH26W-25S-0.3SHW(60)  [FH26W-25S-0_3SHW_60]  83.17 96.35 180 top
J0301  -  [W-N3-SC90-012]  50.03 8.12 0 top
J0302  -  [WX4558105890]  36.28 1.95 0 top
J0401  -  [WXHDMI2034A36]  9.7 5.38 0 top
J0402  50552-00601-001  [50552-00601-001_PINS8_7D5X3D4]  48.6 96.47 180 top
J0403  50552-04001-001  [50552-04001-001_PINS42_24D5X3D4]  65.1 96.28 0 top
J0501  -  [AXE530127]  28.68 96.72 0 top
J0502  NM-50552-03001-001  [50552-03001-001_PINS32_19D5X3D4]  10.43 46.12 90 bottom
J0503  04 6298 706 220 883+  [6298706220883]  41.35 95.62 180 top
J0601  W-USB2-SZ90-A10  [W-USB2-SZ90-A10_PINS12_17D85X14D3]  89.72 8.3 0 top
J0701  0679105700  [MINI-PCIE-CON]  94.28 31.65 0 top
J0702  0480995701  [480995701]  94.28 82.05 0 top
J0801  -  [MUP-M615-1]  70.4 8.35 0 top
J0802  MUP-C792-36  [MUP-C792-3]  71.39 0.72 90 bottom
J0901  -  [11201208210120021]  107.95 5.85 0 top
J1001  NM-C2001VD10601T0101PB  [C2001VD10601T0101PB]  3.02 60.33 90 top
J1002  KR-CKX-3.5-335D-F  [KR-CKX-3_5-335D-F_PINS6_13D9X9D5]  24.04 4.97 180 top
J1101  NM-PH2542-3-115D30T  [PH2542-3-115D30T]  115.7 59.12 90 top
J1201  NM-C2012VD21222T0101PC  [C2012VD21222T0101PC]  115.25 79.92 90 top
L0101  L  [L-SPM6530T-3R3M]  57.95 86.47 0 bottom
L0102  3.3uH +/-20% 0.0179ohm Isat=8.5A Irms=6.2A  [L-SPM6530T-3R3M]  35.3 59.9 270 bottom
L0103  L  [L-SPM6530T-3R3M]  33.25 82.5 270 bottom
L0201  1.0uH +/-20% 0.038ohm 3.65A  [L-2016]  85.08 89.95 90 bottom
L0401  10uH +/-20% 0.435ohm 0.8A  [L-2520]  71.95 90.65 270 top
L0501  10uH +/-20% 0.435ohm 0.8A  [L-2520]  60.23 69.05 270 bottom
L0601  3.3uH +/-20% 0.0179ohm Isat=8.5A Irms=6.2A  [L-SPM6530T-3R3M]  35.5 44.67 180 bottom
L0701  2.2uH +/-20%  [L-SPM6530T-3R3M]  74.88 32.38 0 bottom
L0702  -  [SDMM0806H-2-900T]  100.05 38.42 90 top
L0901  2.2uH +/-20%  [L-2016]  107.75 48.83 90 bottom
LAB1201  25x10mm Universal Label Paper_GDL  [SILKLABEL_25_00X10_00]  59.88 55.2 180 bottom
PCB1201  -  [BOARD_PCB]  1.48 40.17 0 top
Q0401  PPM3FD20V2  [WPM3027]  63.58 92.25 270 bottom
Q0402  -  [DTC043ZEBTL]  65.35 92.6 270 bottom
Q0403  -  [DTC043ZEBTL]  65.7 94.6 180 bottom
Q0404  NM-DTC043ZEBTL  [DTC043ZEBTL]  46.85 97.2 0 bottom
Q0405  NM-PNMT60V02  [PNMT60V02]  47.52 90.05 90 bottom
Q0501  NM-DMG2305UX-7  [DMG2305UX-7]  14.5 34.3 180 bottom
Q0502  NM-DMG2305UX-7  [DMG2305UX-7]  6.62 47.5 180 bottom
Q1101  NM-DTC043ZEBTL  [DTC043ZEBTL]  99.97 64.55 90 bottom
Q1102  NM-DTC043ZEBTL  [DTC043ZEBTL]  99.97 62.55 90 bottom
R0101  4.7K +/-5% 1/16W  [R-0402]  26.6 83.08 180 bottom
R0102  130K +/-1% 1/16W  [R-0402]  34.77 67.58 270 bottom
R0103  120K +/-5% 1/16W  [R-0402]  50.38 84 0 bottom
R0104  10K +/-5% 1/16W  [R-0402]  26.6 82.22 180 bottom
R0105  47K +/-1% 1/16W  [R-0402]  49.98 85.3 90 bottom
R0106  NM-0R +/-5% 1/4W  [R-1206]  5.45 80.05 0 bottom
R0108  34K +/-1% 1/16W  [R-0402]  26.6 84.78 0 bottom
R0110  120K +/-5% 1/16W  [R-0402]  33.83 67.58 270 bottom
R0112  24.9K +/-1% 1/16W  [R-0402]  35.62 67.58 90 bottom
R0113  10K +/-5% 1/16W  [R-0402]  50.83 82.7 270 bottom
R0114  15K +/-1% 1/16W  [R-0402]  50.83 85.3 270 bottom
R0115  110K +/-1% 1/16W  [R-0402]  26.6 83.92 0 bottom
R0116  3.3K +/-5% 1/16W  [R-0402]  9.15 84.15 0 top
R0117  10K +/-5% 1/16W  [R-0402]  32.75 66.67 270 bottom
R0120  0R +/-1% 1/4W  [R-1206]  16.68 84.08 90 top
R0166  NM-0R +/-5% 1/16W  [R-0402]  51.67 82.7 270 bottom
R0203  10K +/-5% 1/16W  [R-0402]  81.08 87.2 180 bottom
R0204  10K +/-5% 1/16W  [R-0402]  87.1 88.53 0 bottom
R0207  2.2K +/-5% 1/16W  [R-0402]  88.12 95.58 90 bottom
R0208  2.2K +/-5% 1/16W  [R-0402]  88.12 97.33 270 bottom
R0209  600ohm@100MHZ DCR=0.6ohm 300mA  [R-0402]  82.53 94.2 90 bottom
R0212  43K +/-1% 1/16W  [R-0402]  73.38 92.95 0 bottom
R0214  110K +/-1% 1/16W  [R-0402]  88.83 91.42 0 bottom
R0219  34K +/-1% 1/16W  [R-0402]  73.38 92.1 180 bottom
R0221  2.2K +/-5% 1/16W  [R-0402]  88.97 95.58 90 bottom
R0222  2.2K +/-5% 1/16W  [R-0402]  88.97 97.33 270 bottom
R0223  10K +/-5% 1/16W  [R-0402]  77.03 87.15 180 bottom
R0224  120K +/-1% 1/16W  [R-0402]  89.75 90.45 180 bottom
R0226  1K +/-5% 1/16W  [R-0402]  77.95 96.55 90 bottom
R0227  1.2K +/-1% 1/16W  [R-0402]  78.8 96.55 270 bottom
R0228  10K +/-5% 1/16W  [R-0402]  73.38 87.15 0 bottom
R0229  600ohm@100MHZ DCR=0.6ohm 300mA  [R-0402]  81.67 94.2 90 bottom
R0255  0R +/-5% 1/16W  [R-0402]  99.03 92.12 90 top
R0256  0R +/-5% 1/16W  [R-0402]  96.17 92.12 90 top
R0257  0R +/-5% 1/16W  [R-0402]  95.33 92.12 90 top
R0258  0R +/-5% 1/16W  [R-0402]  92.47 92.12 90 top
R0259  0R +/-5% 1/16W  [R-0402]  91.62 92.12 90 top
R0260  0R +/-5% 1/16W  [R-0402]  88.78 92.12 90 top
R0261  0R +/-5% 1/16W  [R-0402]  87.58 92.22 90 top
R0262  0R +/-5% 1/16W  [R-0402]  84.72 92.22 90 top
R0263  0R +/-5% 1/16W  [R-0402]  81.03 92.22 90 top
R0264  0R +/-5% 1/16W  [R-0402]  83.88 92.22 90 top
R0265  0R +/-5% 1/16W  [R-0402]  77.33 92.22 90 top
R0266  0R +/-5% 1/16W  [R-0402]  80.17 92.22 90 top
R0302  10K +/-5% 1/16W  [R-0402]  32.92 9.88 180 top
R0305  NM-47K +/-5% 1/16W  [R-0402]  30.98 19.07 90 bottom
R0308  47K +/-5% 1/16W  [R-0402]  30.98 17.32 270 bottom
R0309  NM-47K +/-5% 1/16W  [R-0402]  32.67 20.18 270 bottom
R0312  15K +/-5% 1/16W  [R-0402]  32.02 10.72 0 top
R0313  NM-4.7K +/-5% 1/16W  [R-0402]  30.98 15.57 90 bottom
R0319  0R +/-5% 1/16W  [R-0402]  31.82 20.18 270 bottom
R0322  0R +/-5% 1/16W  [R-0402]  55.4 20.62 90 top
R0323  0R +/-5% 1/16W  [R-0402]  54.55 20.62 90 top
R0325  100R +/-5% 1/16W  [R-0402]  38.55 6.85 0 top
R0340  0R +/-5% 1/16W  [R-0402]  50.45 20.7 90 top
R0341  0R +/-5% 1/16W  [R-0402]  51.3 20.7 90 top
R0366  NM-0R +/-5% 1/10W  [R-0603]  35.45 16.62 270 bottom
R0401  1K +/-5% 1/16W  [R-0402]  2.4 18.5 180 bottom
R0402  0R +/-5% 1/16W  [R-0402]  73.95 92.62 270 top
R0403  NM-10K +/-5% 1/16W  [R-0402]  45.45 91.08 270 bottom
R0404  NM-4.7K +/-5% 1/16W  [R-0402]  48.6 92.8 90 bottom
R0405  10K +/-5% 1/16W  [R-0402]  11.12 21.52 90 bottom
R0406  NM-0R +/-5% 1/16W  [R-0402]  67.17 94.53 270 bottom
R0407  10K +/-5% 1/16W  [R-0402]  63.45 90.97 0 bottom
R0408  NM-0R +/-5% 1/10W  [R-0603]  7.88 26.45 180 bottom
R0409  0R +/-5% 1/16W  [R-0402]  47.3 92.35 180 bottom
R0413  5.1R +/-1% 1/16W  [R-0402]  68.6 85.83 90 top
R0414  NM-4.7K +/-5% 1/16W  [R-0402]  49.05 94.1 180 bottom
R0415  NM-4.7K +/-5% 1/16W  [R-0402]  48.75 98.5 180 bottom
R0416  27K +/-1% 1/16W  [R-0402]  12.7 17.43 270 bottom
R0417  10K +/-5% 1/16W  [R-0402]  7.15 21.05 180 bottom
R0418  0R +/-5% 1/16W  [R-0402]  46.4 95.75 180 bottom
R0420  1.8K +/-1% 1/16W  [R-0402]  7.1 17.25 0 bottom
R0421  4.7K +/-5% 1/16W  [R-0402]  61.67 94.67 270 bottom
R0422  10K +/-5% 1/16W  [R-0402]  70.28 90.08 270 top
R0424  0R +/-5% 1/16W  [R-0402]  50.5 98.5 0 bottom
R0425  100K +/-5% 1/16W  [R-0402]  2.4 17.65 180 bottom
R0426  1.8K +/-1% 1/16W  [R-0402]  9.72 17.3 180 bottom
R0427  NM-0R +/-5%  [R-0402]  62.6 92.28 270 bottom
R0428  27K +/-1% 1/16W  [R-0402]  14.55 21.55 90 bottom
R0429  NM-4.7K +/-5% 1/16W  [R-0402]  47.3 94.05 0 bottom
R0430  0R +/-5% 1/16W  [R-0402]  52.27 94.95 0 bottom
R0455  0R +/-5% 1/16W  [R-0402]  16.3 16.43 270 top
R0457  0R +/-5% 1/16W  [R-0402]  12.5 16.43 270 top
R0458  0R +/-5% 1/16W  [R-0402]  9.65 16.43 270 top
R0459  0R +/-5% 1/16W  [R-0402]  8.7 16.43 270 top
R0460  0R +/-5% 1/16W  [R-0402]  5.85 16.43 270 top
R0461  0R +/-5% 1/16W  [R-0402]  4.9 16.43 270 top
R0462  0R +/-5% 1/16W  [R-0402]  2.05 16.43 270 top
R0466  0R +/-5% 1/16W  [R-0402]  13.45 16.43 270 top
R0503  NM-10K +/-5% 1/16W  [R-0402]  6.72 44.62 270 bottom
R0504  NM-10K +/-5% 1/16W  [R-0402]  15.15 97.42 90 top
R0505  NM-100K +/-5% 1/16W  [R-0402]  19.15 50.88 90 top
R0506  NM-10K +/-5% 1/16W  [R-0402]  10.78 35.27 0 bottom
R0507  10K +/-5% 1/16W  [R-0402]  14.7 95.97 0 top
R0508  2.2K +/-5% 1/16W  [R-0402]  38.98 92.1 270 top
R0509  NM-0R +/-5% 1/10W  [R-0603]  4.4 47.25 90 bottom
R0510  NM-10K +/-5% 1/16W  [R-0402]  64.92 83.9 90 bottom
R0511  0R +/-5% 1/16W  [R-0402]  25.7 98.53 0 bottom
R0512  10K +/-5% 1/16W  [R-0402]  62.35 69 0 bottom
R0513  NM-0R +/-5% 1/16W  [R-0402]  17.82 92.47 270 top
R0515  NM-10K +/-5% 1/16W  [R-0402]  13.53 92.47 270 top
R0516  NM-10K +/-5% 1/16W  [R-0402]  15.43 44.85 0 bottom
R0517  2.2K +/-5% 1/16W  [R-0402]  39.83 92.1 270 top
R0518  10K +/-5% 1/16W  [R-0402]  63.42 84.3 0 bottom
R0519  NM-100K +/-5% 1/16W  [R-0402]  19.15 52.62 270 top
R0522  NM-10K +/-5% 1/16W  [R-0402]  11.22 33.73 90 bottom
R0523  0R +/-5% 1/16W  [R-0402]  67.97 72.6 180 bottom
R0525  NM-0R +/-5% 1/10W  [R-0603]  12.2 34.1 90 bottom
R0526  0R +/-5% 1/16W  [R-0402]  63.42 83.45 180 bottom
R0527  NM-4.7K +/-5% 1/16W  [R-0402]  15.43 44 0 bottom
R0528  NM-0R +/-5%  [R-0402]  28.88 97.45 270 bottom
R0529  NM-10K +/-5% 1/16W  [R-0402]  16.6 33.1 90 bottom
R0530  5.1R +/-1% 1/16W  [R-0402]  62.38 72.95 180 bottom
R0566  0R +/-5% 1/16W  [R-0402]  19.38 92.7 90 top
R0567  0R +/-5% 1/16W  [R-0402]  22.23 92.7 90 top
R0568  0R +/-5% 1/16W  [R-0402]  23.07 92.7 90 top
R0569  0R +/-5% 1/16W  [R-0402]  25.93 92.7 90 top
R0570  0R +/-5% 1/16W  [R-0402]  26.77 92.7 90 top
R0571  0R +/-5% 1/16W  [R-0402]  29.62 92.7 90 top
R0572  0R +/-5% 1/16W  [R-0402]  30.48 92.7 90 top
R0573  0R +/-5% 1/16W  [R-0402]  33.33 92.7 90 top
R0574  0R +/-5% 1/16W  [R-0402]  33.92 94.92 90 top
R0575  0R +/-5% 1/16W  [R-0402]  36.77 94.92 90 top
R0601  0R +/-5% 1/16W  [R-0402]  61.77 29.82 270 top
R0602  NM-47K +/-5% 1/16W  [R-0402]  75.25 26.55 90 bottom
R0603  NM-4.7K +/-5% 1/16W  [R-0402]  69.28 24.02 90 bottom
R0604  NM-47K +/-5% 1/16W  [R-0402]  75.25 24.8 270 bottom
R0606  130K +/-1% 1/16W  [R-0402]  37.77 51.23 270 bottom
R0607  NM-47K +/-5% 1/16W  [R-0402]  74.8 27.85 0 bottom
R0608  0R +/-5% 1/16W  [R-0402]  60.8 29.82 270 top
R0610  NM-4.7K +/-5% 1/16W  [R-0402]  38.48 20.07 90 bottom
R0611  0R +/-5% 1/16W  [R-0402]  88.95 19.27 270 top
R0612  NM-47K +/-5% 1/16W  [R-0402]  68.05 26.5 90 bottom
R0613  24.9K +/-1% 1/16W  [R-0402]  38.62 51.23 90 bottom
R0614  NM-47K +/-5% 1/16W  [R-0402]  68.05 24.75 270 bottom
R0615  120K +/-5% 1/16W  [R-0402]  36.92 51.23 270 bottom
R0616  0R +/-5% 1/16W  [R-0402]  88.1 19.27 270 top
R0617  NM-4.7K +/-5% 1/16W  [R-0402]  76.53 24.02 90 bottom
R0618  NM-47K +/-5% 1/16W  [R-0402]  67.62 27.8 0 bottom
R0619  0R +/-5% 1/16W  [R-0402]  46.58 19.65 270 top
R0620  10K +/-5% 1/16W  [R-0402]  36.08 51.23 90 bottom
R0621  0R +/-5% 1/16W  [R-0402]  45.73 19.65 270 top
R0622  NM-47K +/-5% 1/16W  [R-0402]  37.25 21.05 270 bottom
R0623  NM-47K +/-5% 1/16W  [R-0402]  37.25 22.8 90 bottom
R0624  NM-47K +/-5% 1/16W  [R-0402]  37.25 24.65 270 bottom
R0644  NM-0R +/-5% 1/16W  [R-0402]  35.83 49.48 270 bottom
R0666  0R +/-5% 1/10W  [R-0603]  72.55 26.18 270 bottom
R0677  0R +/-5% 1/10W  [R-0603]  79.75 26.05 270 bottom
R0678  0R +/-5% 1/10W  [R-0603]  41.77 22.35 270 bottom
R0698  NM-0R +/-5% 1/16W  [R-0402]  62.23 30.27 0 top
R0699  NM-0R +/-5% 1/16W  [R-0402]  60.35 30.27 180 top
R0701  NM-0R +/-5% 1/16W  [R-0402]  94.9 25.15 180 top
R0702  NM-0R +/-5% 1/16W  [R-0402]  85.97 57.75 270 bottom
R0703  0R +/-5% 1/16W  [R-0402]  104.03 25.4 90 top
R0704  0R +/-5% 1/16W  [R-0402]  96.85 24.27 90 top
R0705  10K +/-5% 1/16W  [R-0402]  95.95 63.45 90 bottom
R0706  NM-0R +/-5% 1/16W  [R-0402]  98.47 24.57 90 top
R0707  NM-0R +/-5% 1/16W  [R-0402]  85.97 59.5 270 bottom
R0708  1K +/-5% 1/16W  [R-0402]  116.5 46.48 0 top
R0709  NM-0R +/-5% 1/16W  [R-0402]  85.95 61.38 90 bottom
R0710  0R +/-5% 1/16W  [R-0402]  104.88 25.4 90 top
R0711  NM-0R +/-5% 1/16W  [R-0402]  86.5 63.7 270 bottom
R0712  NM_51K +/-1% 1/16W  [R-0402]  88.2 63.33 0 bottom
R0713  0R +/-5% 1/16W  [R-0402]  86.42 58.2 0 bottom
R0714  0R +/-5% 1/16W  [R-0402]  105.72 25.4 90 top
R0715  NM-0R +/-5% 1/10W  [R-0603]  111.38 36.02 270 top
R0716  0R +/-5% 1/16W  [R-0402]  86.05 64.15 180 bottom
R0717  34K +/-1% 1/16W  [R-0402]  67.1 32.98 180 bottom
R0718  10K +/-1% 1/16W  [R-0402]  67.1 33.83 0 bottom
R0719  NM-0R +/-5% 1/16W  [R-0402]  86.03 25.65 0 top
R0720  0R +/-5% 1/16W  [R-0402]  86.42 59.95 0 bottom
R0721  0R +/-5% 1/16W  [R-0402]  86.4 60.92 0 bottom
R0722  NM_51K +/-1% 1/16W  [R-0402]  96.4 61.3 0 bottom
R0723  NM_10K +/-5% 1/16W  [R-0402]  66.25 31.27 180 bottom
R0724  0R +/-5% 1/16W  [R-0402]  103.17 25.4 90 top
R0725  120K +/-5% 1/16W  [R-0402]  67.55 31.68 90 bottom
R0726  0R +/-5% 1/16W  [R-0402]  66.25 32.12 0 bottom
R0727  120K +/-5% 1/16W  [R-0402]  96.4 62.15 180 bottom
R0728  NM-0R +/-5% 1/10W  [R-0603]  94.88 38.4 90 top
R0729  0R +/-5% 1/16W  [R-0402]  96.4 59.6 0 bottom
R0730  1K +/-5% 1/16W  [R-0402]  116.5 45.62 0 top
R0731  0R +/-5% 1/16W  [R-0402]  96.4 58.75 0 bottom
R0732  NM-0R +/-5% 1/16W  [R-0402]  96.85 25.18 270 top
R0733  0R +/-5% 1/16W  [R-0402]  96.4 60.45 0 bottom
R0801  33R +/-5% 1/16W  [R-0402]  64.22 18.6 270 top
R0802  33R +/-5% 1/16W  [R-0402]  70.15 18.6 270 top
R0803  0R +/-5% 1/10W  [R-0603]  66.42 21.4 0 bottom
R0804  15K +/-5% 1/16W  [R-0402]  72.03 21.32 90 bottom
R0805  0R +/-5% 1/16W  [R-0402]  73.03 18.6 270 top
R0806  33R +/-5% 1/16W  [R-0402]  72.17 18.6 270 top
R0807  1K +/-5% 1/16W  [R-0402]  67.25 18.15 180 top
R0808  0R +/-5% 1/10W  [R-0603]  73.08 21.68 270 bottom
R0809  NM-10K +/-5% 1/16W  [R-0402]  67.25 19 0 top
R0810  0R +/-5% 1/10W  [R-0603]  68.75 22.5 0 bottom
R0811  33R +/-5% 1/16W  [R-0402]  68.92 18.6 270 top
R0813  0R +/-5% 1/10W  [R-0603]  74.65 20.45 0 top
R0814  33R +/-5% 1/16W  [R-0402]  65.08 18.6 270 top
R0866  NM_51K +/-1% 1/16W  [R-0402]  74.47 20.6 270 bottom
R0901  4.7K +/-5% 1/16W  [R-0402]  113.97 48.2 270 bottom
R0902  NM-4.7K +/-5% 1/16W  [R-0402]  92.9 49.73 180 bottom
R0903  22R +/-5% 1/16W  [R-0402]  95.2 51.02 90 bottom
R0904  4.7K +/-5% 1/16W  [R-0402]  110.42 46.15 180 bottom
R0905  NM-4.7K +/-5% 1/16W  [R-0402]  100.3 51.02 270 bottom
R0906  22R +/-5% 1/16W  [R-0402]  98.6 51.02 90 bottom
R0907  NM-4.7K +/-5% 1/16W  [R-0402]  113.97 49.1 270 bottom
R0908  NM-470R +/-5% 1/16W  [R-0402]  109.58 17.77 90 top
R0909  4.7K +/-5% 1/16W  [R-0402]  94.35 51.02 270 bottom
R0910  0R +/-5% 1/16W  [R-0402]  107.6 52.4 0 bottom
R0911  75R +/-1% 1/16W  [R-0402]  98.92 22.23 90 bottom
R0912  4.7K +/-5% 1/16W  [R-0402]  93.5 51.02 270 bottom
R0913  2.49K +/-1% 1/16W  [R-0402]  108.97 39.38 270 bottom
R0914  NM-4.7K +/-5% 1/16W  [R-0402]  109.97 46.6 90 bottom
R0915  0R +/-5% 1/16W  [R-0402]  91.83 42.45 180 bottom
R0916  NM-4.7K +/-5% 1/16W  [R-0402]  94.65 49.73 180 bottom
R0917  4.7K +/-5% 1/16W  [R-0402]  101.65 49.73 0 bottom
R0918  75R +/-1% 1/16W  [R-0402]  101.92 22.23 90 bottom
R0919  NM-4.7K +/-5% 1/16W  [R-0402]  101.15 51.02 270 bottom
R0920  22R +/-5% 1/16W  [R-0402]  102 51.02 90 bottom
R0921  NM-4.7K +/-5% 1/16W  [R-0402]  96.9 51.02 270 bottom
R0922  470R +/-5% 1/16W  [R-0402]  112.12 17.77 90 top
R0923  0R +/-5% 1/16W  [R-0402]  109.08 51.95 90 bottom
R0924  75R +/-1% 1/16W  [R-0402]  107.92 22.23 90 bottom
R0925  NM-0R +/-5% 1/16W  [R-0402]  111.33 41.2 0 bottom
R0926  NM-120R +/-1% 1/16W  [R-0402]  111.85 45.3 0 bottom
R0927  NM-470R +/-5% 1/16W  [R-0402]  105.8 18.35 180 top
R0928  NM-4.7K +/-5% 1/16W  [R-0402]  97.75 51.02 270 bottom
R0929  4.7K +/-5% 1/16W  [R-0402]  112.67 48.65 0 bottom
R0930  0R +/-5% 1/16W  [R-0402]  104.85 19.2 0 top
R0931  0R +/-5% 1/16W  [R-0402]  99.38 39.83 180 bottom
R0932  22R +/-5% 1/16W  [R-0402]  92.65 51.02 90 bottom
R0933  NM-0R +/-5% 1/16W  [R-0402]  111.28 17.77 270 top
R0934  NM-100R +/-5% 1/16W  [R-0402]  110.1 45.3 0 bottom
R0935  NM-0R +/-5% 1/16W  [R-0402]  110.8 50.8 0 bottom
R0936  NM-1M +/-5% 1/16W  [R-0402]  108.97 43.05 90 bottom
R0938  470R +/-5% 1/16W  [R-0402]  103.6 17.9 270 top
R0939  0R +/-5% 1/16W  [R-0402]  110.42 17.77 270 top
R0940  4.7K +/-5% 1/16W  [R-0402]  99.9 49.73 180 bottom
R0941  4.7K +/-5% 1/16W  [R-0402]  110.8 51.65 180 bottom
R0942  4.7K +/-5% 1/16W  [R-0402]  102.45 42.55 270 top
R0943  75R +/-1% 1/16W  [R-0402]  104.92 22.23 90 bottom
R0944  4.7K +/-5% 1/16W  [R-0402]  96.4 49.73 180 bottom
R0945  22R +/-5% 1/16W  [R-0402]  99.45 51.02 90 bottom
R0946  1M +/-5% 1/16W  [R-0402]  113.42 18.23 180 top
R0947  1.5K +/-5% 1/16W  [R-0402]  97.6 40.52 0 bottom
R0948  NM-0R +/-5% 1/16W  [R-0402]  111.67 39.02 270 bottom
R0949  0R +/-5% 1/16W  [R-0402]  97.6 39.67 180 bottom
R0950  NM-0R +/-5% 1/16W  [R-0402]  92.67 44.2 0 bottom
R0951  NM-0R +/-5% 1/16W  [R-0402]  104.45 17.9 270 top
R0952  4.7K +/-5% 1/16W  [R-0402]  98.15 49.73 180 bottom
R0953  4.7K +/-5% 1/16W  [R-0402]  112.22 50.85 90 bottom
R0954  0R +/-5% 1/16W  [R-0402]  92.67 43.35 180 bottom
R0955  22R +/-5% 1/16W  [R-0402]  96.05 51.02 90 bottom
R0956  NM-4.7K +/-5% 1/16W  [R-0402]  112.22 49.1 270 bottom
R0988  NM-0R +/-5% 1/16W  [R-0402]  109.28 49.12 270 bottom
R1002  NM-7.5R  [R-0805]  13.22 61.02 270 bottom
R1003  0R +/-5% 1/16W  [R-0402]  17.02 91.05 0 top
R1004  NM-47K +/-5% 1/16W  [R-0402]  12.8 73.5 180 bottom
R1005  NM-47K +/-5% 1/10W  [R-0603]  20.93 70.55 0 bottom
R1007  NM-10K +/-1% 1/16W  [R-0402]  11.03 72.55 0 bottom
R1008  NM-0R +/-5% 1/8W  [R-0805]  8.9 72.28 90 bottom
R1010  0R +/-5% 1/16W  [R-0402]  22.23 14.07 0 top
R1011  NM-10K +/-1% 1/16W  [R-0402]  12.9 72.55 0 bottom
R1012  NM-47K +/-5% 1/10W  [R-0603]  8.68 68.62 0 bottom
R1014  1K +/-5% 1/16W  [R-0402]  20.25 14.22 180 top
R1015  NM-3.9K +/-5% 1/16W  [R-0402]  7.67 70.9 270 bottom
R1016  NM-7.5R  [R-0805]  9.12 66.58 90 bottom
R1017  10K +/-1% 1/16W  [R-0402]  20.25 15.93 180 top
R1018  0R +/-5% 1/16W  [R-0402]  24.02 13.12 0 top
R1019  NM-7.5R  [R-0805]  19.52 61.92 0 bottom
R1020  NM-7.5R  [R-0805]  11.62 61.02 270 bottom
R1021  NM-0R +/-5% 1/8W  [R-0805]  14.62 72.33 90 bottom
R1022  NM-2K +/-5% 1/16W  [R-0402]  6.7 70.9 90 bottom
R1023  0R +/-5% 1/16W  [R-0402]  29.77 9.65 270 top
R1024  NM-47K +/-5% 1/16W  [R-0402]  14.68 75.12 180 bottom
R1099  0R +/-5% 1/16W  [R-0402]  18.3 89.2 0 top
R1103  NM-10K +/-5% 1/16W  [R-0402]  100.5 60.62 270 bottom
R1105  NM-22R +/-5% 1/16W  [R-0402]  103 61.08 180 bottom
R1107  10K +/-5% 1/16W  [R-0402]  105.55 56.75 270 bottom
R1111  NM-22R +/-5% 1/16W  [R-0402]  103.5 67.17 180 bottom
R1113  NM-1K +/-5% 1/16W  [R-0402]  108.25 64.9 270 bottom
R1115  0R +/-5% 1/16W  [R-0402]  104.7 55.05 270 bottom
R1117  NM-10K +/-5% 1/16W  [R-0402]  103.5 68.03 180 bottom
R1119  0R +/-5% 1/16W  [R-0402]  103 55.05 90 bottom
R1120  NM-200R +/-5% 1/16W  [R-0402]  108.3 71.05 180 bottom
R1121  NM-47K +/-5% 1/10W  [R-0603]  98.35 63.3 90 bottom
R1123  NM-120R +/-1% 1/16W  [R-0402]  109.1 63.98 90 bottom
R1125  NM-0R +/-5% 1/16W  [R-0402]  99.45 60.62 270 bottom
R1126  0R +/-5% 1/16W  [R-0402]  103.85 55.05 90 bottom
R1129  NM-1K +/-5% 1/16W  [R-0402]  108.25 63.12 90 bottom
R1130  0R +/-5% 1/16W  [R-0402]  102.15 55.05 90 bottom
R1132  120K +/-5% 1/16W  [R-0402]  106.85 57.2 0 bottom
R1133  NM-200R +/-5% 1/16W  [R-0402]  108.3 70.2 180 bottom
R1134  NM-0R +/-5%  [R-0402]  101.75 67.17 0 bottom
R1155  NM-0R +/-5% 1/16W  [R-0402]  102.67 58.88 270 bottom
R1156  0R +/-5% 1/16W  [R-0402]  101.83 58.88 90 bottom
R1157  NM-0R +/-5% 1/16W  [R-0402]  103.55 58.88 270 bottom
R1158  0R +/-5% 1/16W  [R-0402]  104.4 58.88 90 bottom
R1159  NM-0R +/-5% 1/16W  [R-0402]  105.25 58.88 270 bottom
R1160  0R +/-5% 1/16W  [R-0402]  106.1 58.88 90 bottom
R1161  NM-0R +/-5% 1/16W  [R-0402]  107.42 59.12 180 bottom
R1162  0R +/-5% 1/16W  [R-0402]  107.42 58.27 0 bottom
R1202  NM-0R +/-5% 1/16W  [R-0402]  86.1 74.03 270 bottom
R1203  2.2K +/-5% 1/16W  [R-0402]  87.62 70.53 0 bottom
R1204  NM-10K +/-5% 1/16W  [R-0402]  84.55 67.67 0 bottom
R1205  NM-0R +/-5% 1/16W  [R-0402]  85.25 74.03 270 bottom
R1206  2.2K +/-5% 1/16W  [R-0402]  87.62 71.38 0 bottom
R1207  NM-0R +/-5% 1/16W  [R-0402]  87.2 68.72 270 bottom
R1208  1K +/-5% 1/16W  [R-0402]  102.22 89.9 0 top
R1210  NM-0R +/-5% 1/16W  [R-0402]  82.12 69.2 90 bottom
R1211  NM-0R +/-5% 1/16W  [R-0402]  81.28 69.2 90 bottom
R1301  NM-0R  [R-0402]  82.03 72.5 270 bottom
R1302  22R +/-5% 1/16W  [R-0402]  99.35 43.62 180 bottom
R1303  22R +/-5% 1/16W  [R-0402]  99.35 42.77 180 bottom
R1304  22R +/-5% 1/16W  [R-0402]  99.35 41.92 180 bottom
R1305  22R +/-5% 1/16W  [R-0402]  99.35 41.08 180 bottom
R1306  22R +/-5% 1/16W  [R-0402]  99.35 44.48 180 bottom
R1307  22R +/-5% 1/16W  [R-0402]  99.35 45.33 180 bottom
R1401  2.2R +/-5% 1/16W  [R-0402]  43.27 75.85 90 top
R1402  2.2R +/-5% 1/16W  [R-0402]  44.12 75.85 90 top
R1403  2.2R +/-5% 1/16W  [R-0402]  41.48 75.85 90 top
R1404  2.2R +/-5% 1/16W  [R-0402]  45.92 75.85 90 top
R1405  2.2R +/-5% 1/16W  [R-0402]  38.6 75.4 180 top
R1406  2.2R +/-5% 1/16W  [R-0402]  38.6 76.25 180 top
R1407  0R +/-5% 1/16W  [R-0402]  31.3 29.9 180 top
R1408  2.2R +/-5% 1/16W  [R-0402]  42.33 75.85 90 top
R1409  2.2R +/-5% 1/16W  [R-0402]  45.08 75.85 90 top
R1455  10K +/-5% 1/16W  [R-0402]  38.48 27.82 180 top
R1456  5.1K +/-5% 1/16W  [R-0402]  38.48 28.68 0 top
R1457  NM-0R +/-5% 1/16W  [R-0402]  38.48 29.52 180 top
R1466  NM-10K +/-5% 1/16W  [R-0402]  42.73 39.38 90 bottom
R1467  NM-10K +/-5% 1/16W  [R-0402]  41.88 39.38 90 bottom
R1468  NM-10K +/-5% 1/16W  [R-0402]  44.02 39.1 0 bottom
R1469  NM-10K +/-5% 1/16W  [R-0402]  44.02 38.25 180 bottom
S0301  -  [SSAJ120100]  116.65 31.23 90 top
S1201  -  [SSAJ120100]  116.72 39.4 90 top
S1202  THDP08-060AB1  [THDP08-060AB1_PINS4_7D5X8D7]  105 94.95 180 top
TP0101  TP_1_00mm  [TP_1_00]  32.83 54.42 90 bottom
TP0102  TP_1_00mm  [TP_1_00]  11.3 84.2 180 top
TP0103  TP_1_00mm  [TP_1_00]  56.62 91.33 180 bottom
TP0104  -  [TP_2_20]  2.27 80.72 0 top
TP0301  TP_1_00mm  [TP_1_00]  35.17 7.78 0 top
TP0302  TP_1_00mm  [TP_1_00]  36.98 7.78 0 top
TP0303  TP_1_00mm  [TP_1_00]  33.95 11.85 0 top
TP0501  -  [TP_1_00]  7.17 54.23 270 bottom
TP0502  TP_1_00mm  [TP_1_00]  34 98.25 0 top
TP0503  -  [TP_1_00]  13.88 42.73 270 bottom
TP0504  TP_1_00mm  [TP_1_00]  23.7 98.65 0 top
TP0701  SLEEP_IND  [TP_1_00]  93.53 24.02 0 top
TP0702  UART_RI  [TP_1_00]  92.08 24.88 0 top
TP0703  WAKEUP_IN  [TP_1_00]  83.2 25.6 0 top
TP1201  TP_1_00mm  [TP_1_00]  113.03 38.65 0 top
TP1202  TP_1_00mm  [TP_1_00]  114.15 40.95 0 top
TP1203  TP_1_00mm  [TP_1_00]  99.15 89.9 0 top
TP1301  TP_1_00mm  [TP_1_00]  21.38 46.08 0 top
TP1302  TP_1_00mm  [TP_1_00]  21.38 47.75 0 top
TP1303  TP_1_00mm  [TP_1_00]  19.7 46.08 0 top
